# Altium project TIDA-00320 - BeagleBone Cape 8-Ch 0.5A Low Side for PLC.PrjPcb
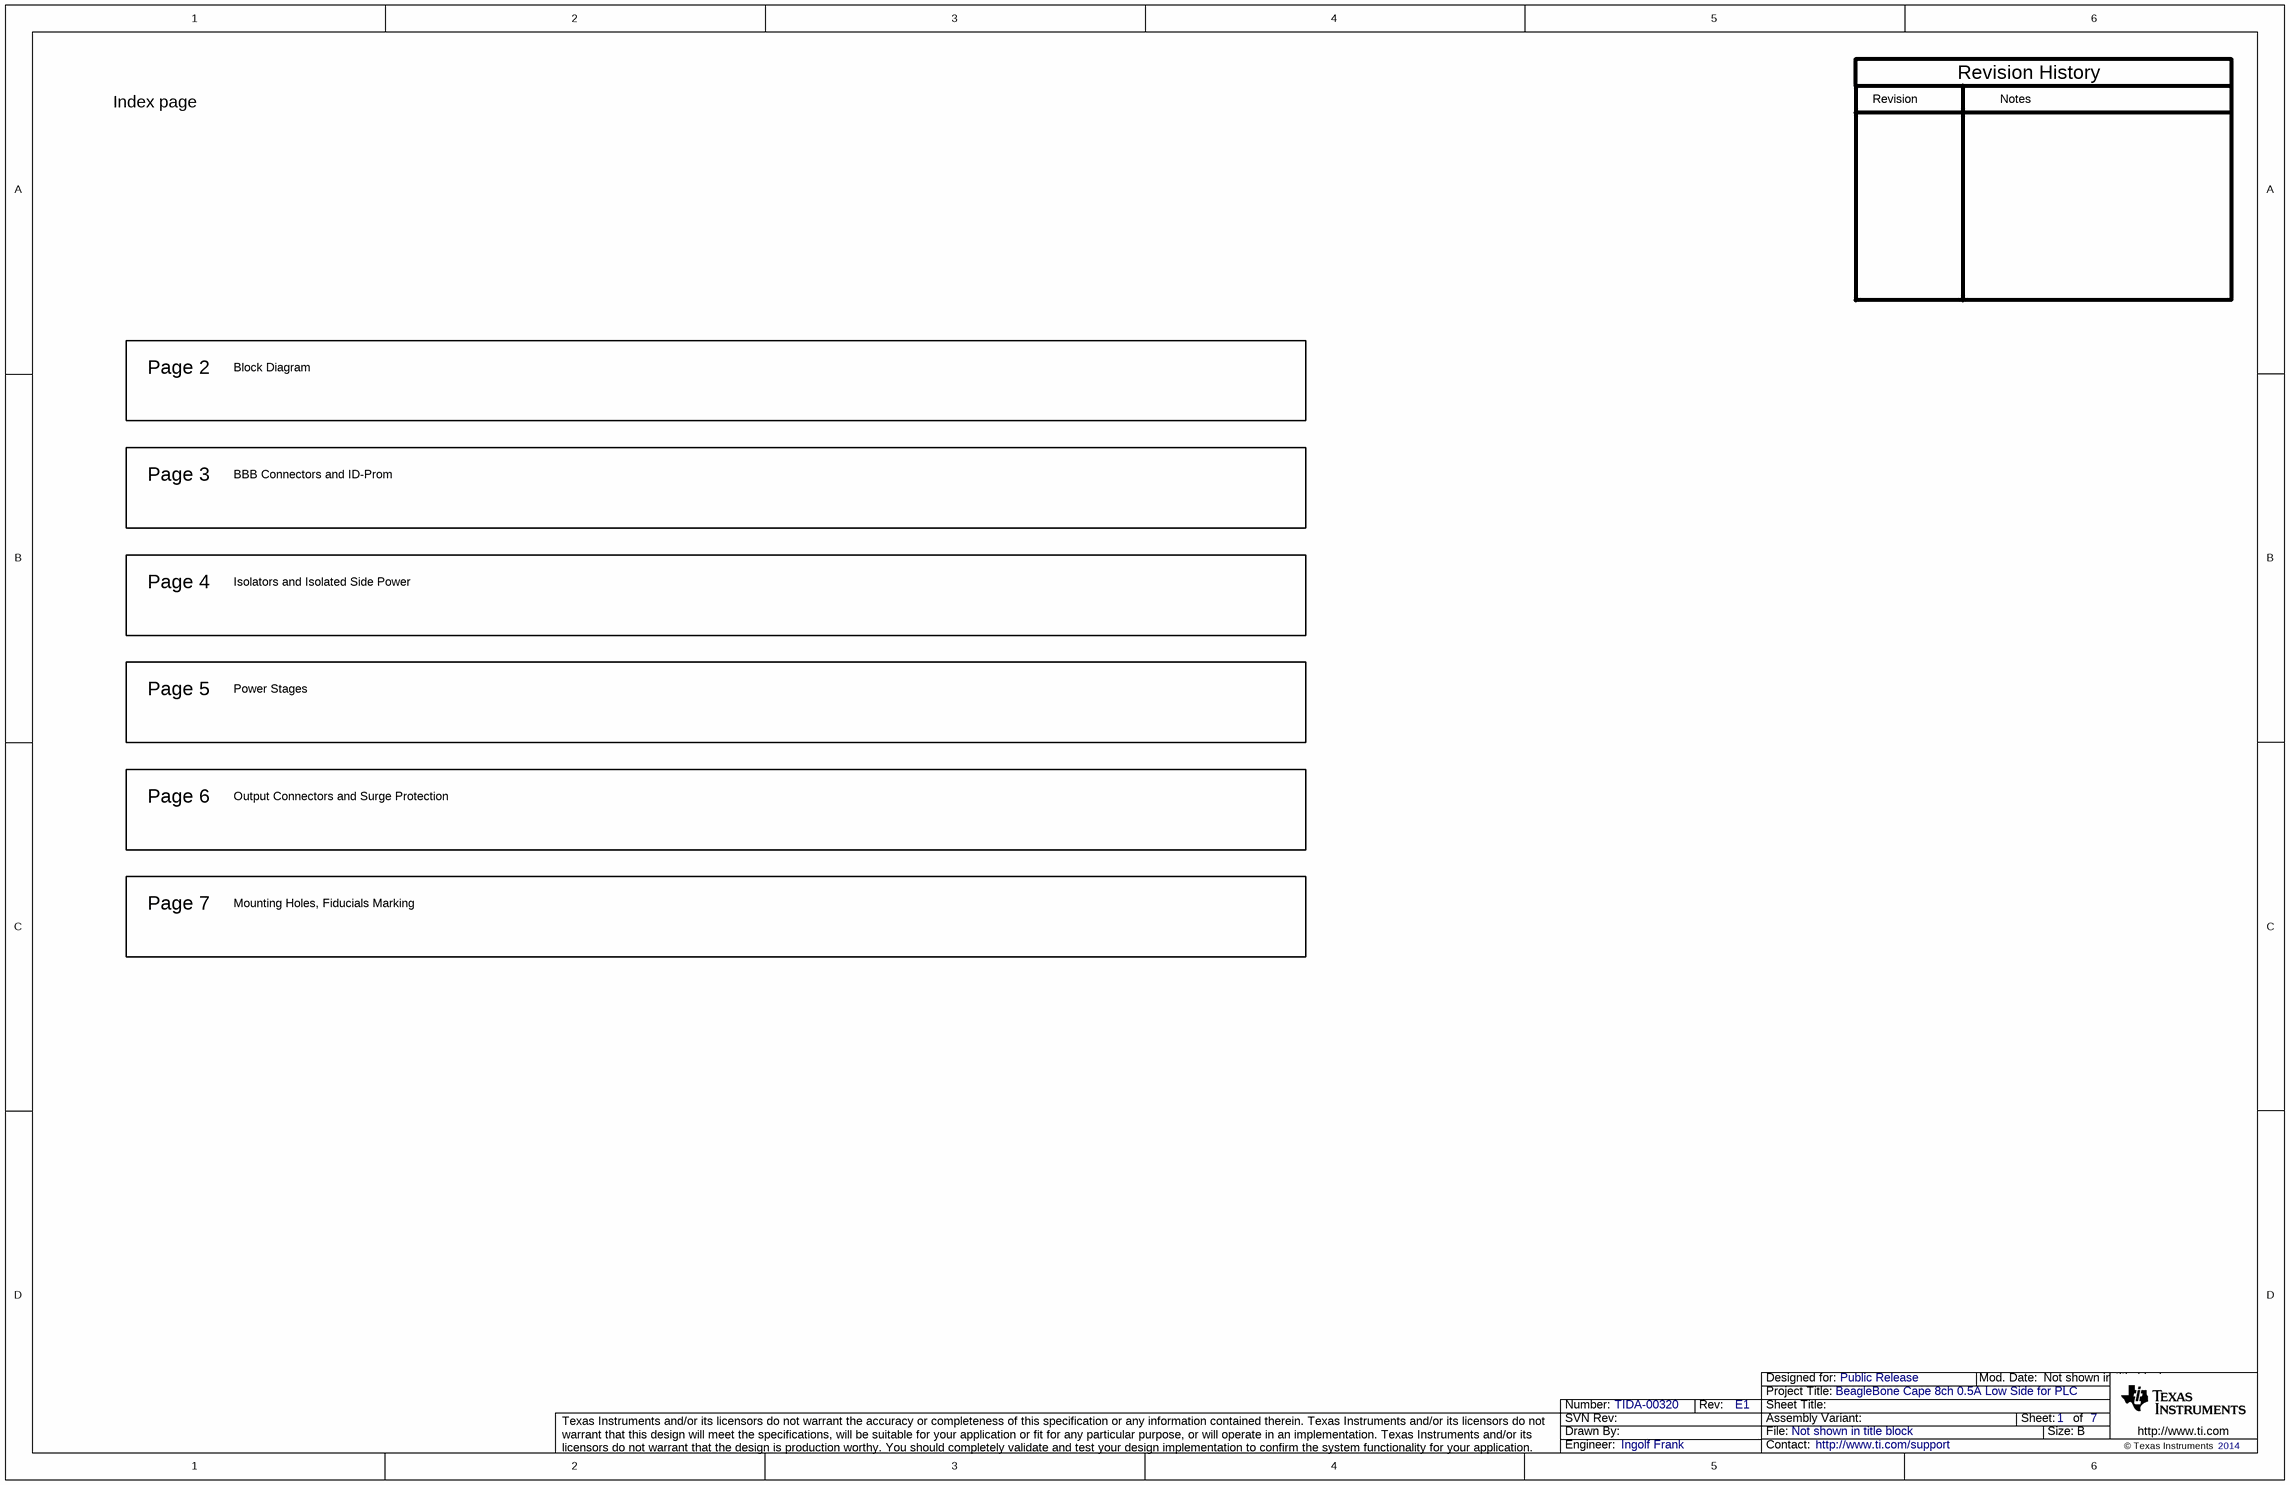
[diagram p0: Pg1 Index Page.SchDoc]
CopyrightYear: 2014; EVM_Orderable: N/A; PCB_Layout: Ingolf Frank; PCB_Rev: E1; PRJ_Customer: Public Release; PRJ_Engineer: Ingolf Frank; PRJ_Number: TIDA-00320; PRJ_Title: BeagleBone Cape 8ch 0.5A Low Side for PLC; SCH_Rev: E1; TechSupport: http://www.ti.com/support; TID: N/A
7 sheets, 117 parts. Net scope: global (net labels, ports and power ports of the same name join across sheets).
Board file: TIDA-00320_BeagleBone_Cape_8ch_LS.PcbDoc
Sheets:
  Pg1 Index Page.SchDoc
  Pg2 Block Diagram.SchDoc
  Pg3 BB Connectors.SchDoc
  Pg4 Cape Power Supply.SchDoc
  Pg5 Cape Power Stages.SchDoc
  Pg6 Cape Output.SchDoc
  Pg7 Hardware.SchDoc

## Sheet Pg1 Index Page.SchDoc
size 431 x 279 mm; Date: Not shown in title block; ApprovedBy: Not shown in title block; CheckedBy: Not shown in title block; Author: Not shown in title block; CompanyName: Not shown in title block; Engineer: Not shown in title block; Organization: Not shown in title block; Address1: Not shown in title block; Address2: Not shown in title block; Address3: Not shown in title block; Address4: Not shown in title block; DocumentNumber: 1; Revision: Use project parameter SCH_Rev; SheetNumber: 1; SheetTotal: 7; PageSetup: Record=PageOptions¦CenterHorizontal=True¦CenterVertical=True¦PrintScale=1.00¦XCorrection=1.00¦YCorrection=1.00¦PrintKind=0¦BorderSize=5000000¦LeftOffset=0¦BottomOffset=0¦Orientation=2¦PaperLength=1000¦PaperWidth=1000¦Scale=100¦PaperSource=15¦PrintQuality=600¦MediaType=1¦DitherType=10¦PaperKind=Letter¦PrintScaleMode=1

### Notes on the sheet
- Revision
- Notes
- Revision History
- Index page
- Page 2
- Block Diagram
- Page 3
- BBB Connectors and ID-Prom
- Page 4
- Isolators and Isolated Side Power
- Page 5
- Power Stages
- Page 6
- Output Connectors and Surge Protection
- Page 7
- Mounting Holes, Fiducials Marking

## Sheet Pg2 Block Diagram.SchDoc
size 431 x 279 mm; Date: Not shown in title block; ApprovedBy: Not shown in title block; CheckedBy: Not shown in title block; Author: Not shown in title block; CompanyName: Not shown in title block; Engineer: Not shown in title block; Organization: Not shown in title block; Address1: Not shown in title block; Address2: Not shown in title block; Address3: Not shown in title block; Address4: Not shown in title block; DocumentNumber: 2; Revision: Use project parameter SCH_Rev; SheetNumber: 2; SheetTotal: 7; PageSetup: Record=PageOptions¦CenterHorizontal=True¦CenterVertical=True¦PrintScale=1.00¦XCorrection=1.00¦YCorrection=1.00¦PrintKind=0¦BorderSize=5000000¦LeftOffset=0¦BottomOffset=0¦Orientation=2¦PaperLength=1000¦PaperWidth=1000¦Scale=100¦PaperSource=15¦PrintQuality=600¦MediaType=1¦DitherType=10¦PaperKind=Letter¦PrintScaleMode=1
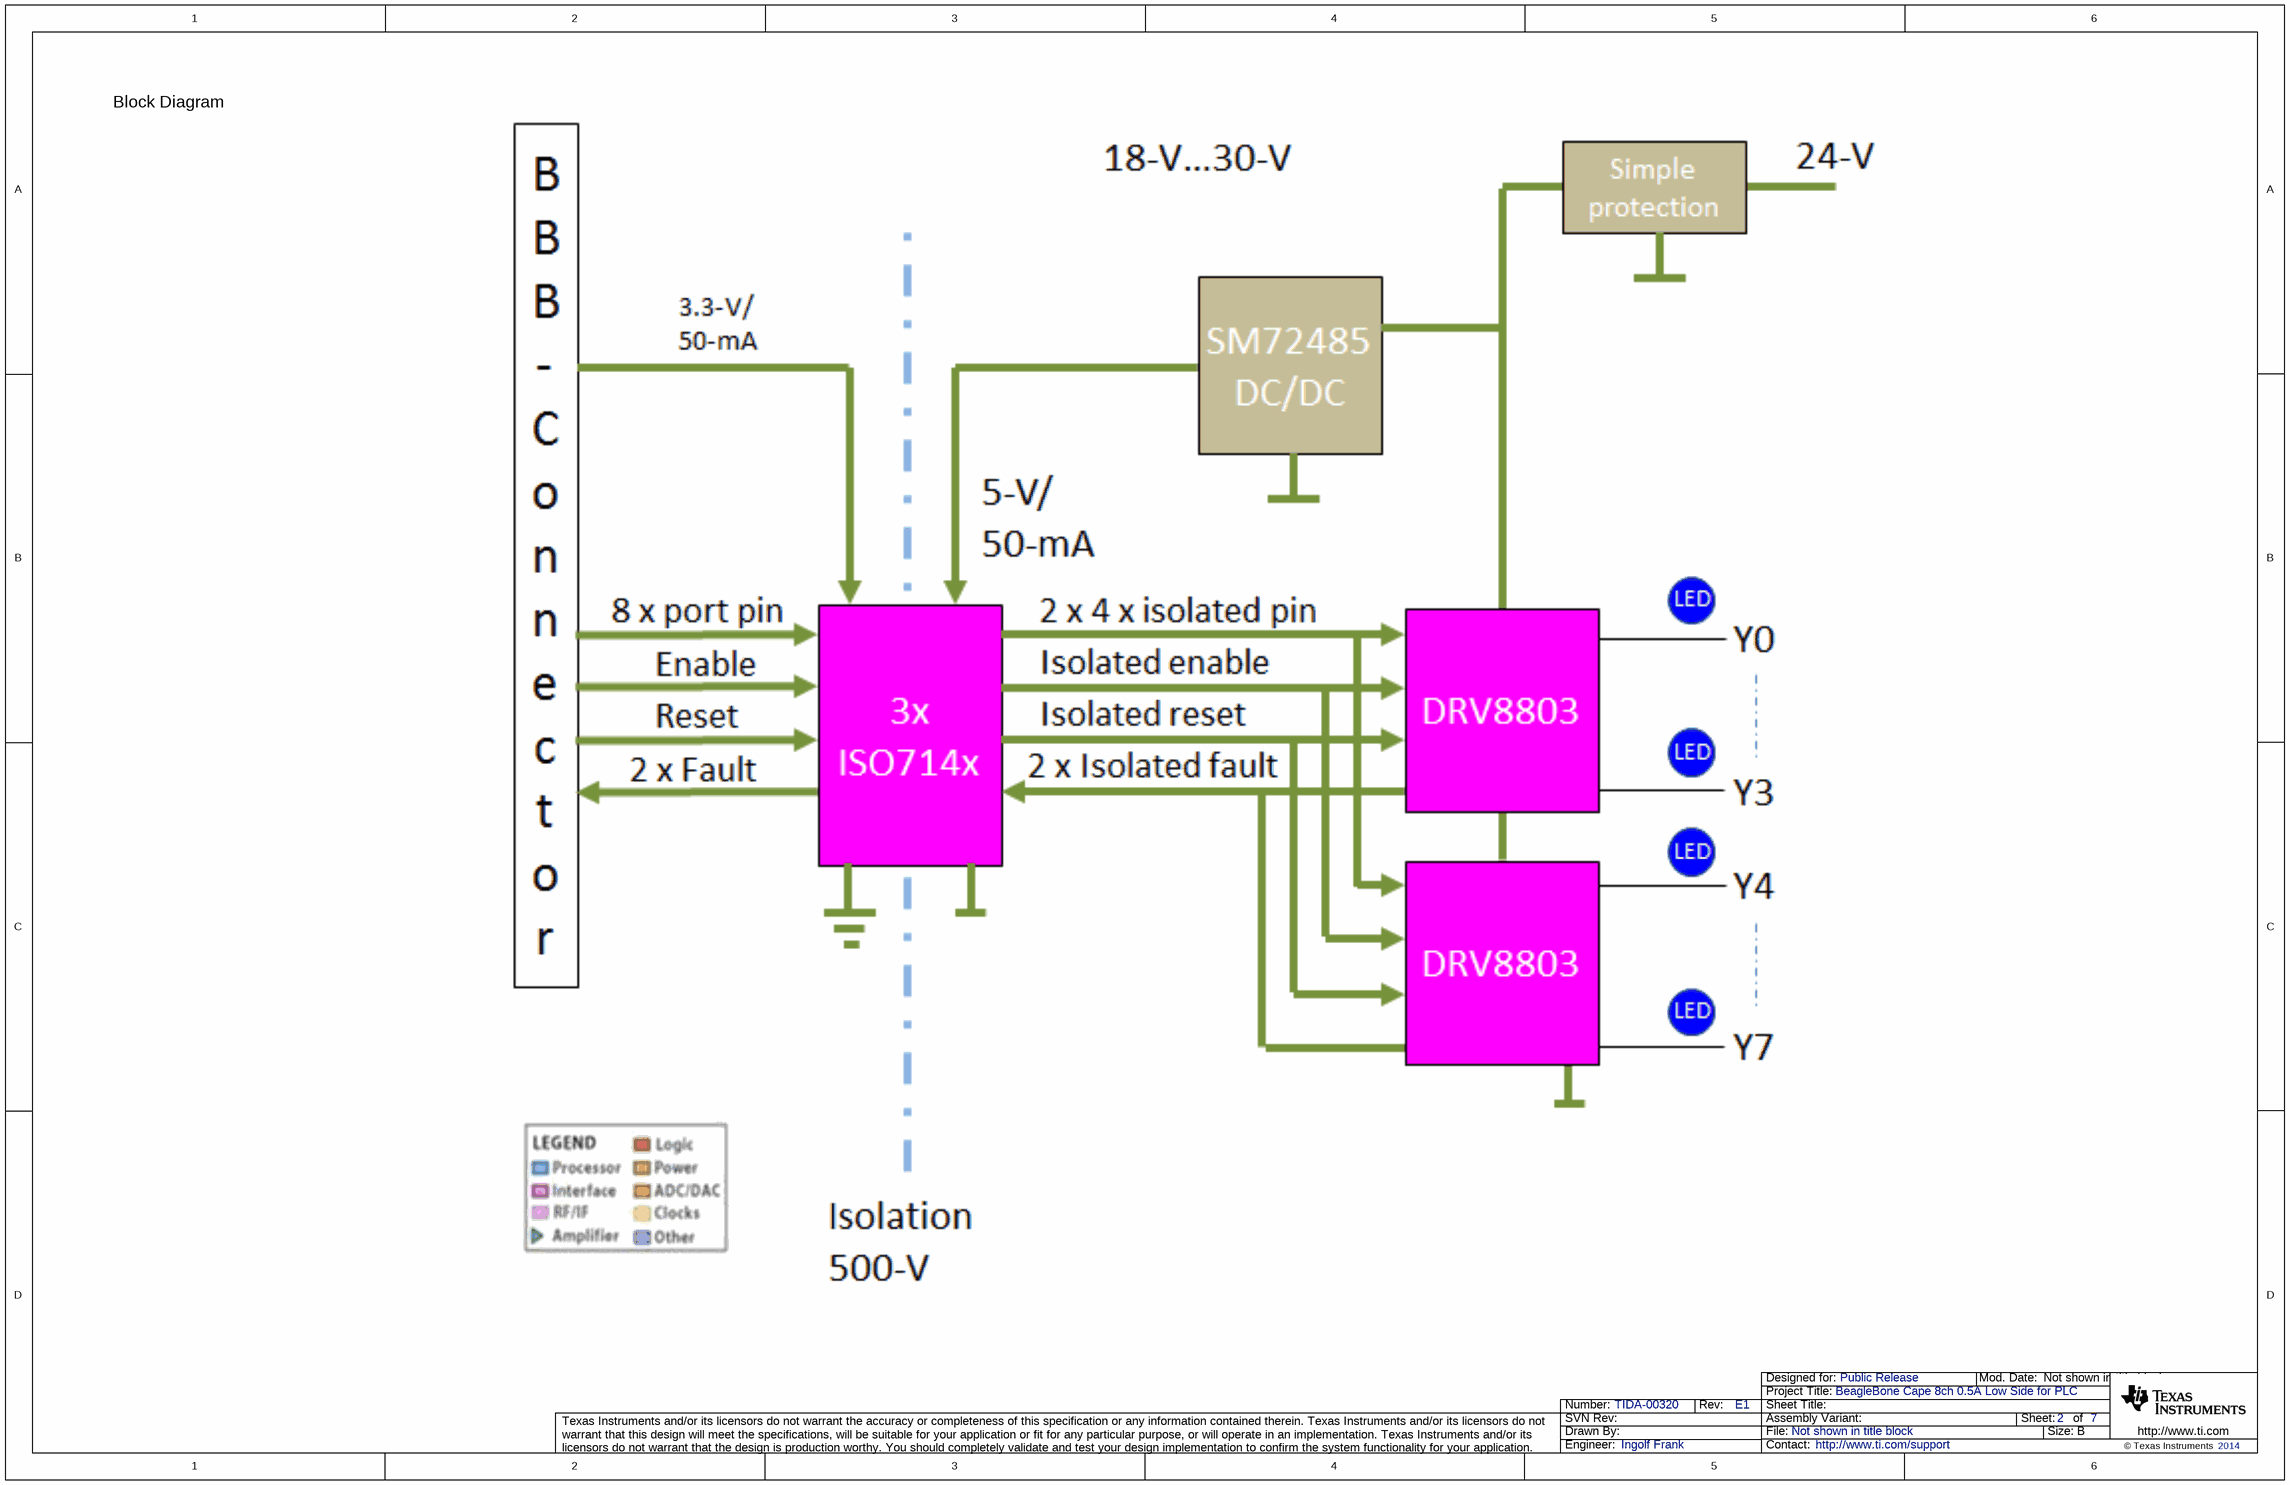
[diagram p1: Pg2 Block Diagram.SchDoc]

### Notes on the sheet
- Block Diagram

## Sheet Pg3 BB Connectors.SchDoc
size 431 x 279 mm; Date: Not shown in title block; ApprovedBy: Not shown in title block; CheckedBy: Not shown in title block; Author: Not shown in title block; CompanyName: Not shown in title block; Engineer: Not shown in title block; Organization: Not shown in title block; Address1: Not shown in title block; Address2: Not shown in title block; Address3: Not shown in title block; Address4: Not shown in title block; DocumentNumber: 3; Revision: Use project parameter SCH_Rev; SheetNumber: 3; SheetTotal: 7; PageSetup: Record=PageOptions¦CenterHorizontal=True¦CenterVertical=True¦PrintScale=1.00¦XCorrection=1.00¦YCorrection=1.00¦PrintKind=0¦BorderSize=5000000¦LeftOffset=0¦BottomOffset=0¦Orientation=2¦PaperLength=1000¦PaperWidth=1000¦Scale=100¦PaperSource=15¦PrintQuality=600¦MediaType=1¦DitherType=10¦PaperKind=Letter¦PrintScaleMode=1
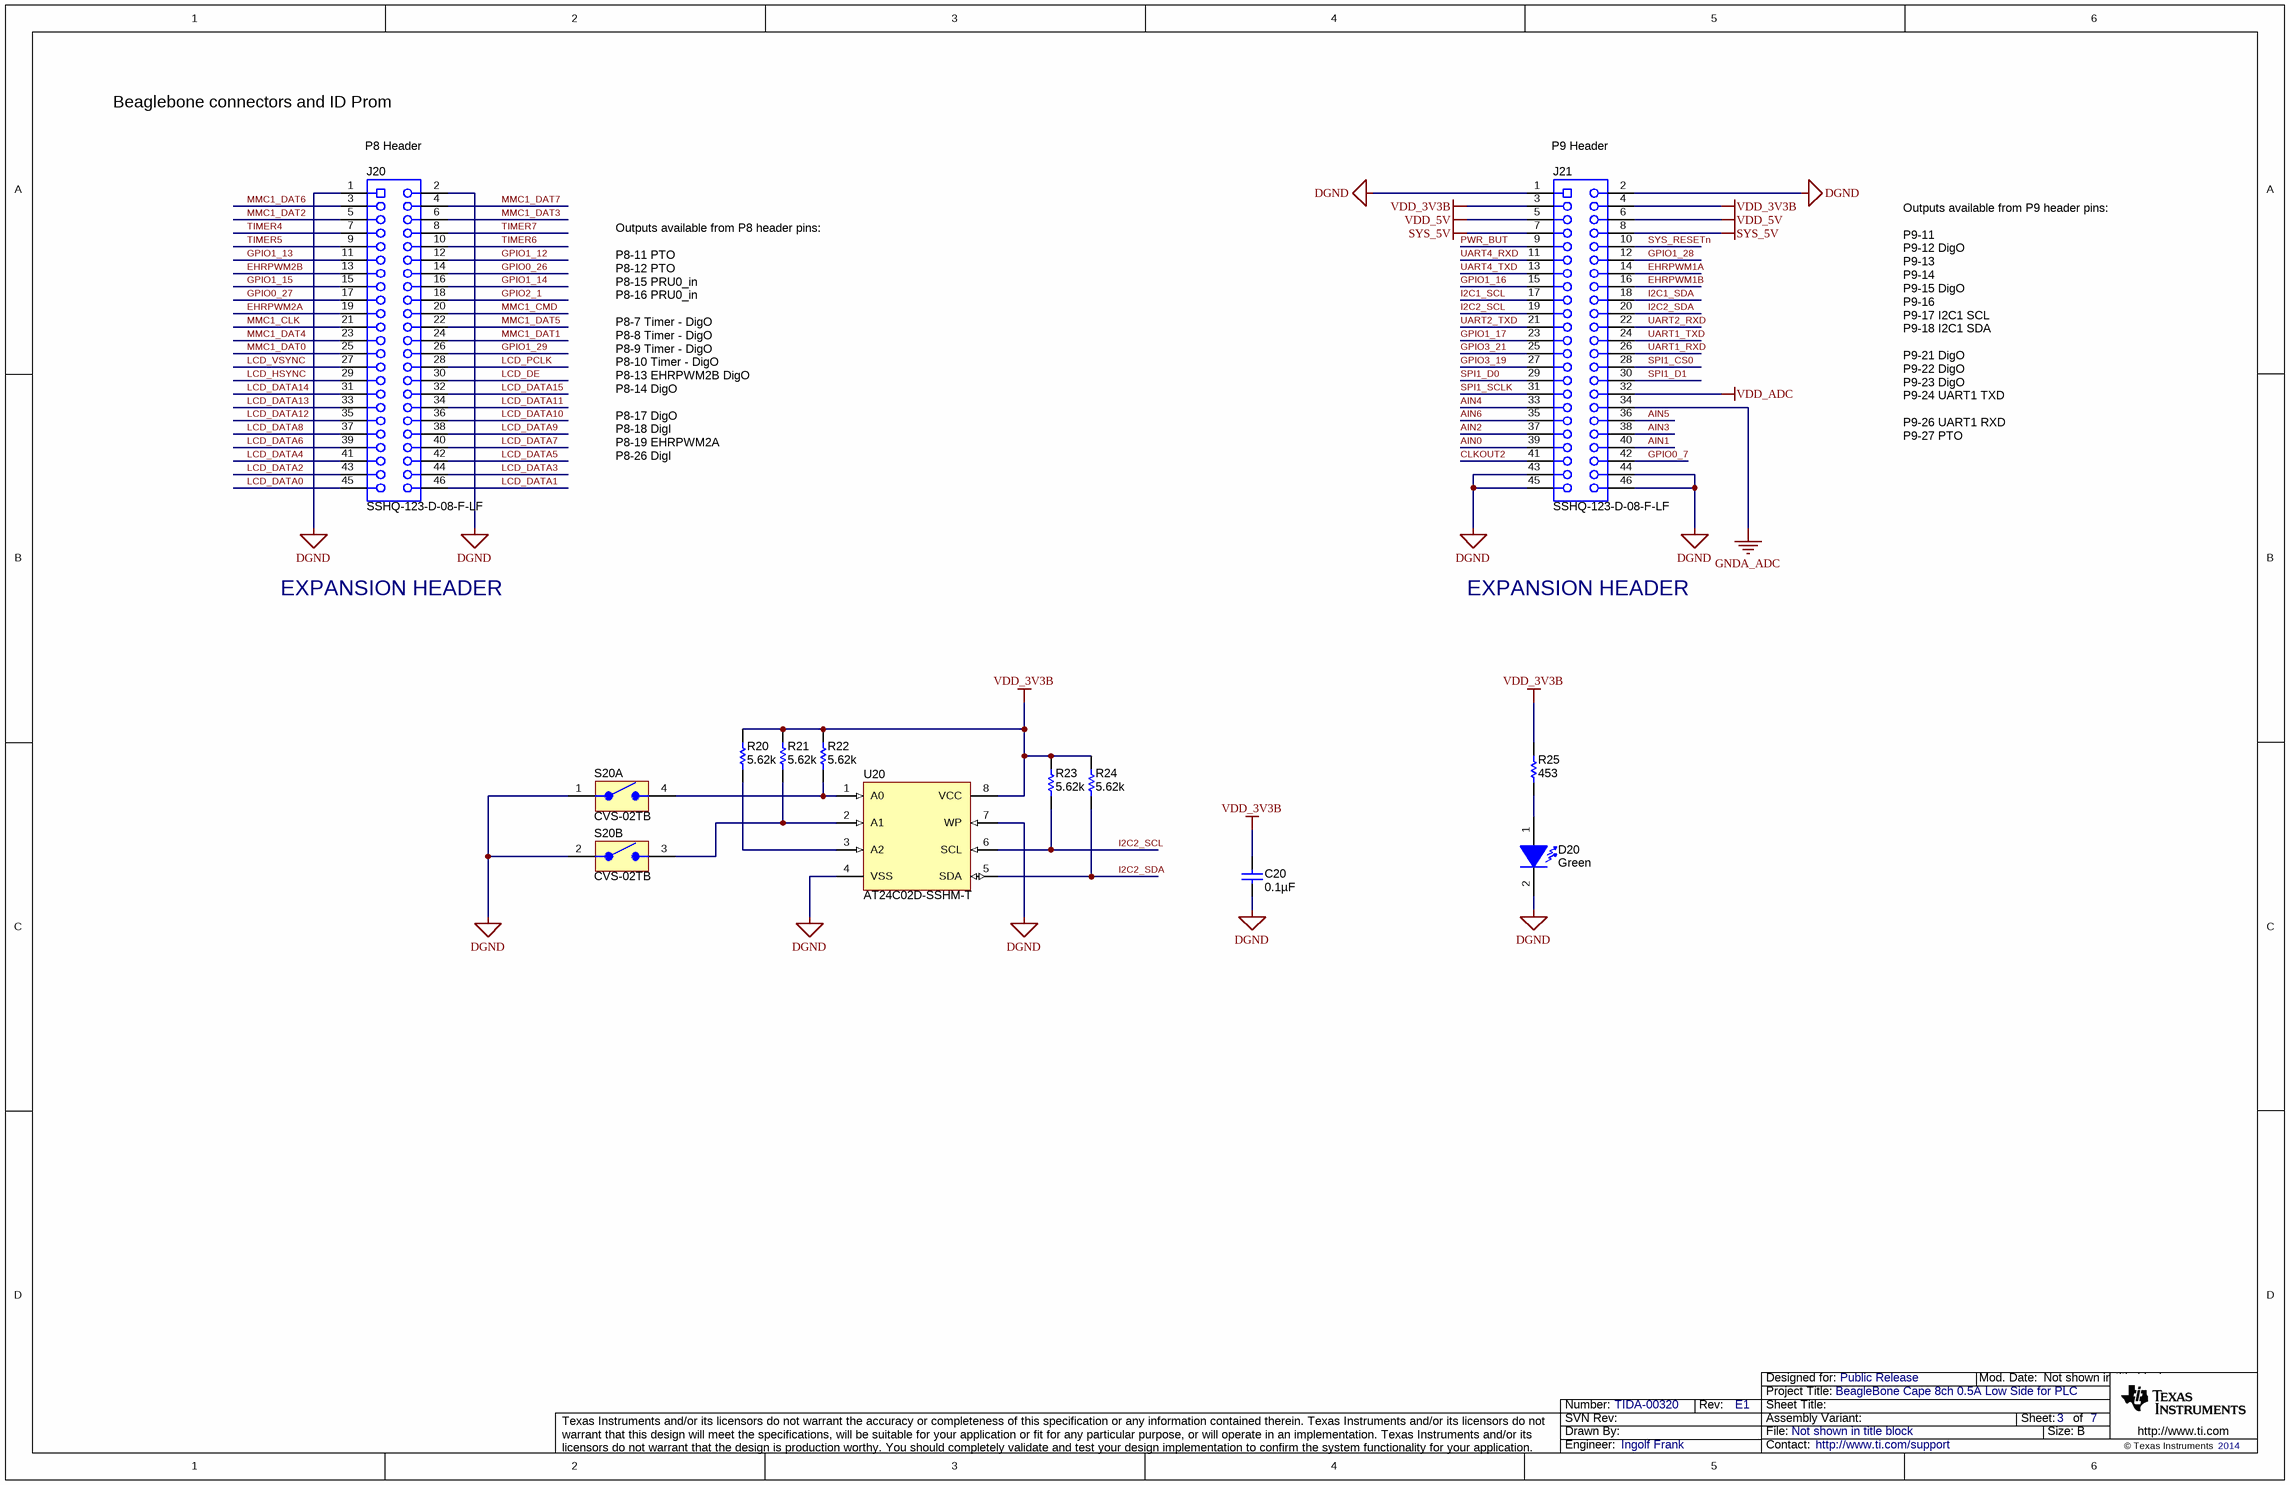
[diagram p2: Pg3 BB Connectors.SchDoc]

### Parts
C20  ValueDisplayed: 0.1µF  [0603]  (hidden comment: C0603C104K5RACTU)
D20  value Green  [LED_LTST-C190_G]  (hidden comment: LTST-C190KGKT)
J20  SSHQ-123-D-08-F-LF  [Major_SSHQ-123-D-08]
J21  SSHQ-123-D-08-F-LF  [Major_SSHQ-123-D-08]
R20  ValueDisplayed: 5.62k  [0603]  (hidden comment: CRCW06035K62FKEA)
R21  ValueDisplayed: 5.62k  [0603]  (hidden comment: CRCW06035K62FKEA)
R22  ValueDisplayed: 5.62k  [0603]  (hidden comment: CRCW06035K62FKEA)
R23  ValueDisplayed: 5.62k  [0603]  (hidden comment: CRCW06035K62FKEA)
R24  ValueDisplayed: 5.62k  [0603]  (hidden comment: CRCW06035K62FKEA)
R25  ValueDisplayed: 453  [0603]  (hidden comment: CRCW0603453RFKEA)
S20  CVS-02TB  [SW_CVS-02B]  (parts A,B of 2)
U20  AT24C02D-SSHM-T  [SOIC-8]

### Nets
DGND: C20.2 D20.2(K) J20.1 J20.2 J21.1 J21.2 J21.43 J21.44 J21.45 J21.46 S20.1 S20.2 U20.4(VSS) U20.7(WP)
GNDA_ADC: J21.34
SYS_5V: J21.7 J21.8
VDD_3V3B: C20.1 J21.3 J21.4 R20.2 R21.2 R22.2 R23.2 R24.2 R25.2 U20.8(VCC)
VDD_5V: J21.5 J21.6
VDD_ADC: J21.32
AIN0: J21.39
AIN1: J21.40
AIN2: J21.37
AIN3: J21.38
AIN4: J21.33
AIN5: J21.36
AIN6: J21.35
CLKOUT2: J21.41
EHRPWM1A: J21.14
EHRPWM1B: J21.16
EHRPWM2A: J20.19
EHRPWM2B: J20.13
GPIO0_7: J21.42
GPIO0_26: J20.14
GPIO0_27: J20.17
GPIO1_12: J20.12
GPIO1_13: J20.11
GPIO1_14: J20.16
GPIO1_15: J20.15
GPIO1_16: J21.15
GPIO1_17: J21.23
GPIO1_28: J21.12
GPIO1_29: J20.26
GPIO2_1: J20.18
GPIO3_19: J21.27
GPIO3_21: J21.25
I2C1_SCL: J21.17
I2C1_SDA: J21.18
I2C2_SCL: J21.19 R23.1 U20.6(SCL)
I2C2_SDA: J21.20 R24.1 U20.5(SDA)
LCD_DATA0: J20.45
LCD_DATA1: J20.46
LCD_DATA2: J20.43
LCD_DATA3: J20.44
LCD_DATA4: J20.41
LCD_DATA5: J20.42
LCD_DATA6: J20.39
LCD_DATA7: J20.40
LCD_DATA8: J20.37
LCD_DATA9: J20.38
LCD_DATA10: J20.36
LCD_DATA11: J20.34
LCD_DATA12: J20.35
LCD_DATA13: J20.33
LCD_DATA14: J20.31
LCD_DATA15: J20.32
LCD_DE: J20.30
LCD_HSYNC: J20.29
LCD_PCLK: J20.28
LCD_VSYNC: J20.27
MMC1_CLK: J20.21
MMC1_CMD: J20.20
MMC1_DAT0: J20.25
MMC1_DAT1: J20.24
MMC1_DAT2: J20.5
MMC1_DAT3: J20.6
MMC1_DAT4: J20.23
MMC1_DAT5: J20.22
MMC1_DAT6: J20.3
MMC1_DAT7: J20.4
PWR_BUT: J21.9
SPI1_CS0: J21.28
SPI1_D0: J21.29
SPI1_D1: J21.30
SPI1_SCLK: J21.31
SYS_RESETn: J21.10
TIMER4: J20.7
TIMER5: J20.9
TIMER6: J20.10
TIMER7: J20.8
UART1_RXD: J21.26
UART1_TXD: J21.24
UART2_RXD: J21.22
UART2_TXD: J21.21
UART4_RXD: J21.11
UART4_TXD: J21.13
NetD20_1: D20.1(A) R25.1
NetR20_1: R20.1 U20.3(A2)
NetR21_1: R21.1 S20.3 U20.2(A1)
NetR22_1: R22.1 S20.4 U20.1(A0)

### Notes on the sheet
- Beaglebone connectors and ID Prom
- (near J20) P8 Header
- (near J21) P9 Header
- Outputs available from P8 header pins:
  P8-11 PTO
  P8-12 PTO
  P8-15 PRU0_in
  P8-16 PRU0_in
  P8-7 Timer - DigO
  P8-8 Timer - DigO
  P8-9 Timer - DigO
  P8-10 Timer - DigO
  P8-13 EHRPWM2B DigO
  P8-14 DigO
  P8-17 DigO
  P8-18 DigI
  P8-19 EHRPWM2A
  P8-26 DigI
- Outputs available from P9 header pins:
  P9-11
  P9-12 DigO
  P9-13
  P9-14
  P9-15 DigO
  P9-16
  P9-17 I2C1 SCL
  P9-18 I2C1 SDA
  P9-21 DigO
  P9-22 DigO
  P9-23 DigO
  P9-24 UART1 TXD
  P9-26 UART1 RXD
  P9-27 PTO
  P9-41 PTO
- EXPANSION HEADER

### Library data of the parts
C20 = C0603C104K5RACTU: CAP, CERM, 0.1 µF, 50 V, +/- 10%, X7R, 0603; Manufacturer: Kemet; Polarized: N; CompType: Capacitor; Value: 0.1uF; U/M: EA; Cap_F: 0.0000001; Tolerance_%: 10; Value1: Unknown; VDC_V: 50; Value2: 50V; TaMin_C: -55; TaMax_C: 125
D20 = LTST-C190KGKT: LED, Green, SMD; Manufacturer: Lite-On; Type: AlInGaP; Vf_V: 2; Value2: 2V; Io_A: 0.03; Tjmax_C: 85; Value1: W; U/M: EA
J20 J21 = SSHQ-123-D-08-F-LF: Female Connector, 2.54mm, 23x2, TH; Manufacturer: Major League Electronics; SymbolCreator: Altium; CompType: Receptacle; U/M: EA
R20-R24 = CRCW06035K62FKEA: RES, 5.62 k, 1%, 0.1 W, 0603; Manufacturer: Vishay-Dale; CompType: Resistor; Value: 5.62k; Res_ohm: 5620; Value_Code: 5k62; Tolerance_%: 1; Power_W: 0.1; Value2: 0.1W; VDC_V: 75; TempCo: 100 ppm/C; EIA_Code: E96; U/M: EA
R25 = CRCW0603453RFKEA: RES, 453, 1%, 0.1 W, 0603; Manufacturer: Vishay-Dale; CompType: Resistor; Value: 453; Value_Code: 453R; Tolerance_%: 1; Power_W: 0.1; Value2: 0.1W; VDC_V: 75; TempCo: 100 ppm/C; EIA_Code: E96; U/M: EA
S20 = CVS-02TB: DIP Switch, SPST, 2Pos, Slide, SMT; Manufacturer: Copal Electronics; SymbolCreator: x0208325; VDC_V: 6; SwitchFunction: Off-On; PositionCount: 2; CurrentRating_mA: 100
U20 = AT24C02D-SSHM-T: I2C-Compatible (2-wire) Serial EEPROM 2-Kbit (256 x 8), SOIC-8; Manufacturer: Atmel; SymbolCreator: a0411947

## Sheet Pg4 Cape Power Supply.SchDoc
size 431 x 279 mm; Date: Not shown in title block; ApprovedBy: Not shown in title block; CheckedBy: Not shown in title block; Author: Not shown in title block; CompanyName: Not shown in title block; Engineer: Not shown in title block; Organization: Not shown in title block; Address1: Not shown in title block; Address2: Not shown in title block; Address3: Not shown in title block; Address4: Not shown in title block; DocumentNumber: 4; Revision: Use project parameter SCH_Rev; SheetNumber: 4; SheetTotal: 7; PageSetup: Record=PageOptions¦CenterHorizontal=True¦CenterVertical=True¦PrintScale=0.64¦XCorrection=1.00¦YCorrection=1.00¦PrintKind=0¦BorderSize=5000000¦LeftOffset=0¦BottomOffset=0¦Orientation=2¦PaperLength=1000¦PaperWidth=1000¦Scale=100¦PaperSource=15¦PrintQuality=600¦MediaType=1¦DitherType=10¦PrintScaleMode=1¦PaperKind=Letter
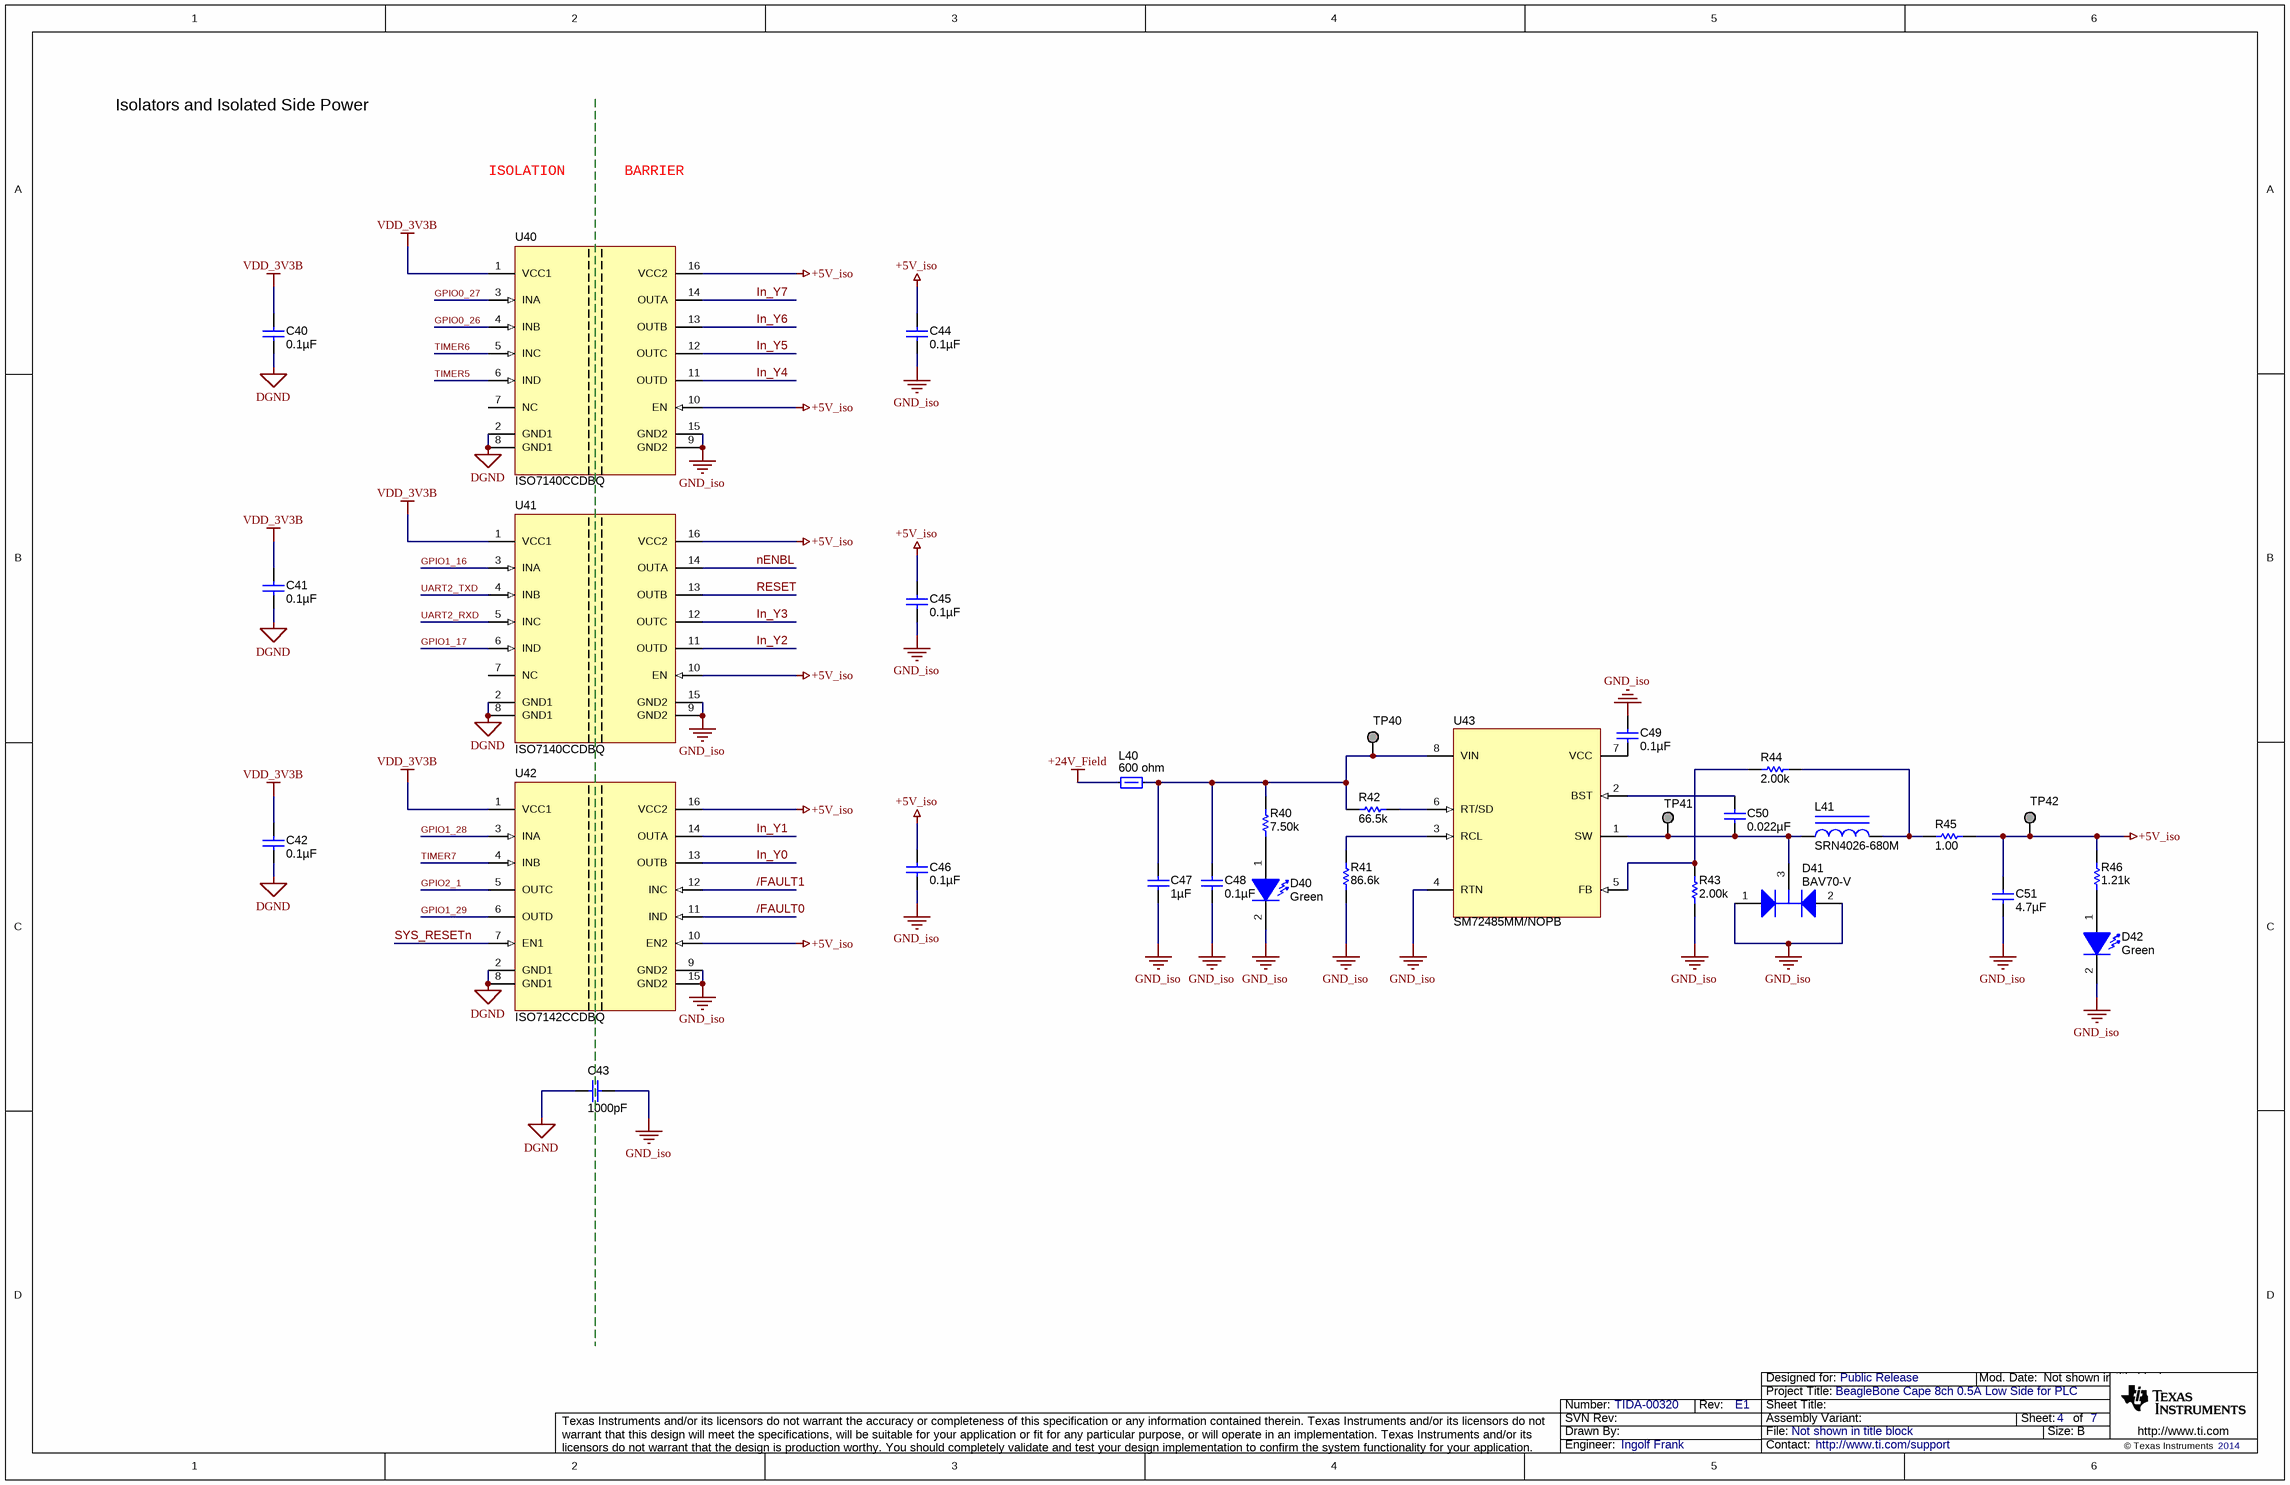
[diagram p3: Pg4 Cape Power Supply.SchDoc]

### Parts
C40  ValueDisplayed: 0.1µF  [0603]  (hidden comment: C0603C104K5RACTU)
C41  ValueDisplayed: 0.1µF  [0603]  (hidden comment: C0603C104K5RACTU)
C42  ValueDisplayed: 0.1µF  [0603]  (hidden comment: C0603C104K5RACTU)
C43  value 1000pF  [1206]  (hidden comment: 202R18W102KV4E)
C44  ValueDisplayed: 0.1µF  [0603]  (hidden comment: C0603C104K5RACTU)
C45  ValueDisplayed: 0.1µF  [0603]  (hidden comment: C0603C104K5RACTU)
C46  ValueDisplayed: 0.1µF  [0603]  (hidden comment: C0603C104K5RACTU)
C47  ValueDisplayed: 1µF  [1206]  (hidden comment: C3216X7R1H105K)
C48  ValueDisplayed: 0.1µF  [0603]  (hidden comment: C0603C104K5RACTU)
C49  ValueDisplayed: 0.1µF  [0603]  (hidden comment: C0603C104K5RACTU)
C50  ValueDisplayed: 0.022µF  [0603]  (hidden comment: C0603C223K5RACTU)
C51  ValueDisplayed: 4.7µF  [0603]  (hidden comment: C0603C475K8PACTU)
D40  value Green  [LED_LTST-C190_G]  (hidden comment: LTST-C190KGKT)
D41  BAV70-V  [SOT-23]
D42  value Green  [LED_LTST-C190_G]  (hidden comment: LTST-C190KGKT)
L40  value 600 ohm  [0603]  (hidden comment: BLM18KG601SN1D)
L41  SRN4026-680M  [SRN4026]
R40  ValueDisplayed: 7.50k  [0603]  (hidden comment: CRCW06037K50FKEA)
R41  value 86.6k  [0603]  (hidden comment: CRCW060386K6FKEA)
R42  value 66.5k  [0603]  (hidden comment: CRCW060366K5FKEA)
R43  ValueDisplayed: 2.00k  [0603]  (hidden comment: CRCW06032K00FKEA)
R44  ValueDisplayed: 2.00k  [0603]  (hidden comment: CRCW06032K00FKEA)
R45  ValueDisplayed: 1.00  [0603]  (hidden comment: CRCW06031R00FKEA)
R46  ValueDisplayed: 1.21k  [0603]  (hidden comment: CRCW06031K21FKEA)
TP40  Pogo Pad  [PogoPad]  (value not drawn)  (no BOM)
TP41  Pogo Pad  [PogoPad]  (value not drawn)  (no BOM)
TP42  Pogo Pad  [PogoPad]  (value not drawn)  (no BOM)
U40  ISO7140CCDBQ  [DBQ0016A_N]
U41  ISO7140CCDBQ  [DBQ0016A_N]
U42  ISO7142CCDBQ  [DBQ0016A_N]
U43  SM72485MM/NOPB  [DGK0008A_N]

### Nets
+5V_iso: C44.1 C45.1 C46.1 C51.1 R45.2 R46.1 TP42.1 U40.10(EN) U40.16(VCC2) U41.10(EN) U41.16(VCC2) U42.10(EN2) U42.16(VCC2)
+24V_Field: L40.1
DGND: C40.2 C41.2 C42.2 C43.2 U40.2(GND1) U40.8(GND1) U41.2(GND1) U41.8(GND1) U42.2(GND1) U42.8(GND1)
GND_iso: C43.1 C44.2 C45.2 C46.2 C47.2 C48.2 C49.1 C51.2 D40.2(K) D41.1(A) D41.2(K) D42.2(K) R41.1 R43.1 U40.9(GND2) U40.15(GND2) U41.9(GND2) U41.15(GND2) U42.9(GND2) U42.15(GND2) U43.4(RTN)
VDD_3V3B: C40.1 C41.1 C42.1 U40.1(VCC1) U41.1(VCC1) U42.1(VCC1)
/FAULT0: U42.11(IND)
/FAULT1: U42.12(INC)
GPIO0_26: U40.4(INB)
GPIO0_27: U40.3(INA)
GPIO1_16: U41.3(INA)
GPIO1_17: U41.6(IND)
GPIO1_28: U42.3(INA)
GPIO1_29: U42.6(OUTD)
GPIO2_1: U42.5(OUTC)
In_Y0: U42.13(OUTB)
In_Y1: U42.14(OUTA)
In_Y2: U41.11(OUTD)
In_Y3: U41.12(OUTC)
In_Y4: U40.11(OUTD)
In_Y5: U40.12(OUTC)
In_Y6: U40.13(OUTB)
In_Y7: U40.14(OUTA)
nENBL: U41.14(OUTA)
RESET: U41.13(OUTB)
SYS_RESETn: U42.7(EN1)
TIMER5: U40.6(IND)
TIMER6: U40.5(INC)
TIMER7: U42.4(INB)
UART2_RXD: U41.5(INC)
UART2_TXD: U41.4(INB)
NetC47_1: C47.1 C48.1 L40.2 R40.2 R42.2 TP40.1 U43.8(VIN)
NetC49_2: C49.2 U43.7(VCC)
NetC50_1: C50.1 U43.2(BST)
NetC50_2: C50.2 D41.3(C) L41.1 TP41.1 U43.1(SW)
NetD40_1: D40.1(A) R40.1
NetD42_1: D42.1(A) R46.2
NetL41_2: L41.2 R44.1 R45.1
NetR41_2: R41.2 U43.3(RCL)
NetR42_1: R42.1 U43.6(RT/SD)
NetR43_2: R43.2 R44.2 U43.5(FB)

Not connected (* = marked no-connect by the designer): U40 7(NC); U41 7(NC)

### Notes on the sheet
- Isolators and Isolated Side Power
- ISOLATION       BARRIER

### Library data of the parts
C40-C42 C44-C46 C49 = C0603C104K5RACTU: as C20 on sheet Pg3 BB Connectors
C43 = 202R18W102KV4E: CAP, CERM, 1000pF, 2KV 10% X7R 1206; Manufacturer: Johanson Dielectrics Inc; Polarized: N; CompType: Capacitor; Cap_F: 0.000000001; Tolerance_%: 0
C47 = C3216X7R1H105K: CAP, CERM, 1uF, 50V, +/-10%, X7R, 1206; Manufacturer: TDK; Polarized: N; CompType: Capacitor; U/M: EA; Cap_F: 0.000001; Tolerance_%: 10; ESR_Ohm: 0.01; Value1: 0.01 ohm; VDC_V: 50; IRMS_A: 3.2; TaMin_C: -55; TaMax_C: 125
C48 = C0603C104K5RACTU: CAP, CERM, 0.1uF, 50V, +/-10%, X7R, 0603; Manufacturer: Kemet; Polarized: N; CompType: Capacitor; U/M: EA; Cap_F: 0.0000001; Tolerance_%: 10; Value1: Unknown; VDC_V: 50; TaMin_C: -55; TaMax_C: 125
C50 = C0603C223K5RACTU: CAP, CERM, 0.022 µF, 50 V, +/- 10%, X7R, 0603; Manufacturer: Kemet; Polarized: N; CompType: Capacitor; Value: 0.022uF; U/M: EA; Cap_F: 0.000000022; Tolerance_%: 10; Value1: Unknown; VDC_V: 50; Value2: 50V; TaMin_C: -55; TaMax_C: 125
C51 = C0603C475K8PACTU: CAP, CERM, 4.7 µF, 10 V, +/- 10%, X5R, 0603; Manufacturer: Kemet; Polarized: N; CompType: Capacitor; Value: 4.7uF; U/M: EA; Cap_F: 0.0000047; Tolerance_%: 10; ESR_ohm: 0.006; Value1: 0.006 ohm; Value2: 10V; IRMS_A: 7.24; TaMin_C: -55; TaMax_C: 85
D40 D42 = LTST-C190KGKT: as D20 on sheet Pg3 BB Connectors
D41 = BAV70-V: Diode, Switching, 70 V, 0.25 A, SOT-23; Manufacturer: Vishay-Semiconductor; Value: 70V; SymbolCreator: a0412235; U/M: EA; Vf_V: 1.25; Value1: 0.25A; Value2: 1.25V; Io_A: 0.25; Vr_V: 70; TJmax_C: 150; RJC_CperW: 430
L40 = BLM18KG601SN1D: Ferrite Bead, 600 ohm @ 100 MHz, 1.3 A, 0603; Manufacturer: MuRata; Imax_A: 1.3; DCR_ohm: 0.15; Value1: 0.15 ohm; Value2: 1.3A; ZTyp@100MHz_Ohm: 600
L41 = SRN4026-680M: Inductor, Wirewound, Ferrite, 68uH, 0.35A, 0.852 ohm, SMD; Manufacturer: Bourns; Ind_H: 68.0E-6; ValueDisplayed: 68µH; Imax_A: 0.35; Irms: 0.35A @ 40C rise; Isat: 0.35A @ 30% inductance drop; DCR_ohm: 0.852
R40 = CRCW06037K50FKEA: RES, 7.50 k, 1%, 0.1 W, 0603; Manufacturer: Vishay-Dale; CompType: Resistor; Value: 7.50k; Res_ohm: 7500; Value_Code: 7k50; Tolerance_%: 1; Power_W: 0.1; Value2: 0.1W; VDC_V: 75; TempCo: 100 ppm/C; EIA_Code: E96; U/M: EA
R41 = CRCW060386K6FKEA: RES, 86.6k ohm, 1%, 0.1W, 0603; Manufacturer: Vishay-Dale; CompType: Resistor; Res_ohm: 86600; Value_Code: 86k6; Tolerance_%: 1; Power_W: 0.1; VDC_V: 75; TempCo: 100 ppm/C; EIA_Code: E96; U/M: EA
R42 = CRCW060366K5FKEA: RES, 66.5k ohm, 1%, 0.1W, 0603; Manufacturer: Vishay-Dale; CompType: Resistor; Res_ohm: 66500; Value_Code: 66k5; Tolerance_%: 1; Power_W: 0.1; VDC_V: 75; TempCo: 100 ppm/C; EIA_Code: E96; U/M: EA
R43 R44 = CRCW06032K00FKEA: RES, 2.00 k, 1%, 0.1 W, 0603; Manufacturer: Vishay-Dale; CompType: Resistor; Value: 2.00k; Res_ohm: 2000; Value_Code: 2k00; Tolerance_%: 1; Power_W: 0.1; Value2: 0.1W; VDC_V: 75; TempCo: 100 ppm/C; EIA_Code: E96; U/M: EA
R45 = CRCW06031R00FKEA: RES, 1.00, 1%, 0.1 W, 0603; Manufacturer: Vishay-Dale; CompType: Resistor; Value: 1.00; Res_ohm: 1; Value_Code: 1R00; Power_W: 0.1; Value2: 0.1W; VDC_V: 75; TempCo: 100 ppm/C; EIA_Code: E96; U/M: EA
R46 = CRCW06031K21FKEA: RES, 1.21 k, 1%, 0.1 W, 0603; Manufacturer: Vishay-Dale; CompType: Resistor; Value: 1.21k; Res_ohm: 1210; Value_Code: 1k21; Tolerance_%: 1; Power_W: 0.1; Value2: 0.1W; VDC_V: 75; TempCo: 100 ppm/C; EIA_Code: E96; U/M: EA
TP40-TP42 = PogoPad: Pad for Pogo Pin Connector; SymbolCreator: codlsc
U40 U41 = ISO7140CCDBQ: 4242-VPK Small-Footprint and Low-Power Quad Channels Digital Isolators, DBQ0016A; Alternate Manufacturer: None; Manufacturer: Texas Instruments; SymbolCreator: a0799628; CompType: IC; U/M: EA
U42 = ISO7142CCDBQ: 4242-V PK Small-Footprint and Low-Power Quad Channel Digital Isolator, DBQ0016A; Alternate Manufacturer: None; Manufacturer: Texas Instruments; SymbolCreator: Altium; CompType: IC; U/M: EA
U43 = SM72485MM/NOPB: SolarMagic 100V, 150 mA Constant On-Time Buck Switching Regulator, DGK0008A; Manufacturer: Texas Instruments; CompType: IC; SymbolCreator: Altium; U/M: EA

## Sheet Pg5 Cape Power Stages.SchDoc: LED drivers and power stages
size 431 x 279 mm; Date: Not shown in title block; ApprovedBy: Not shown in title block; CheckedBy: Not shown in title block; Author: Not shown in title block; CompanyName: Not shown in title block; DrawnBy: Ingolf Frank; Engineer: Not shown in title block; Organization: Not shown in title block; Address1: Not shown in title block; Address2: Not shown in title block; Address3: Not shown in title block; Address4: Not shown in title block; DocumentNumber: 5; Revision: Use project parameter SCH_Rev; SheetNumber: 5; SheetTotal: 7; PageSetup: Record=PageOptions¦CenterHorizontal=True¦CenterVertical=True¦PrintScale=0.64¦XCorrection=1.00¦YCorrection=1.00¦PrintKind=0¦BorderSize=5000000¦LeftOffset=0¦BottomOffset=0¦Orientation=2¦PaperLength=1000¦PaperWidth=1000¦Scale=100¦PaperSource=15¦PrintQuality=600¦MediaType=1¦DitherType=10¦PaperKind=Letter¦PrintScaleMode=1
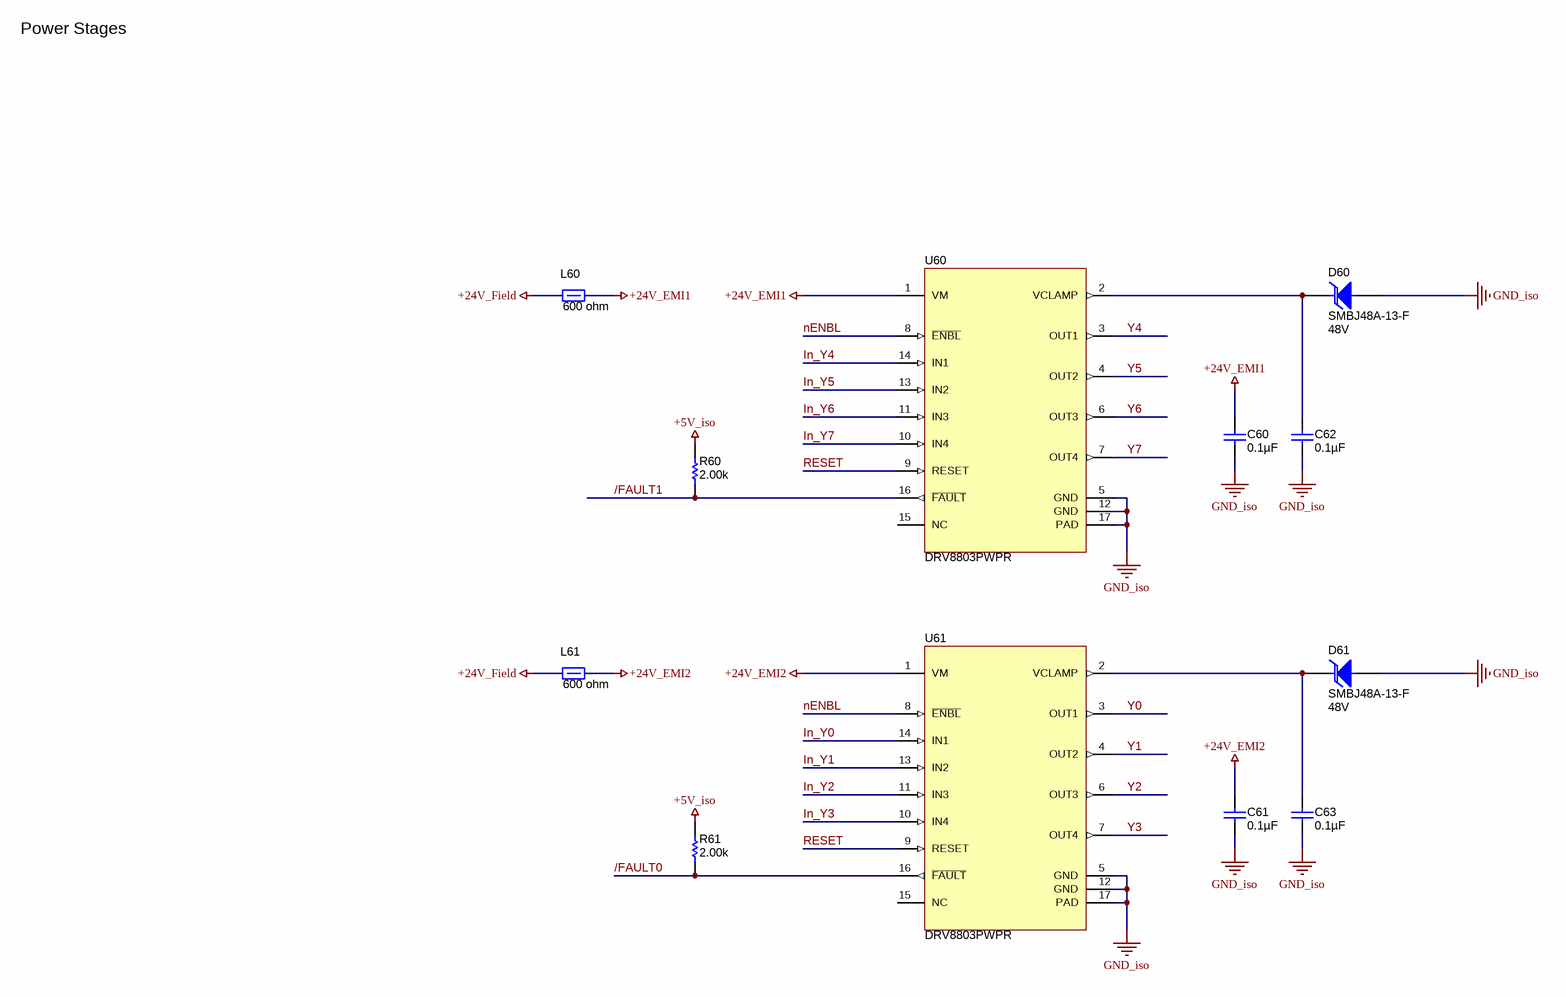
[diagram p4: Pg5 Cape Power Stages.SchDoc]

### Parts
C60  ValueDisplayed: 0.1µF  [0603]  (hidden comment: C0603C104K5RACTU)
C61  ValueDisplayed: 0.1µF  [0603]  (hidden comment: C0603C104K5RACTU)
C62  ValueDisplayed: 0.1µF  [0805_HV]  (hidden comment: CL21B104KCFSFNE)
C63  ValueDisplayed: 0.1µF  [0805_HV]  (hidden comment: CL21B104KCFSFNE)
D60  SMBJ48A-13-F  value 48V  [SMB]
D61  SMBJ48A-13-F  value 48V  [SMB]
L60  value 600 ohm  [0603]  (hidden comment: BLM18KG601SN1D)
L61  value 600 ohm  [0603]  (hidden comment: BLM18KG601SN1D)
R60  ValueDisplayed: 2.00k  [0603]  (hidden comment: CRCW06032K00FKEA)
R61  ValueDisplayed: 2.00k  [0603]  (hidden comment: CRCW06032K00FKEA)
U60  DRV8803PWPR  [PWP0016D_N]
U61  DRV8803PWPR  [PWP0016D_N]

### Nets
+5V_iso: R60.1 R61.1
+24V_EMI1: C60.1 L60.2 U60.1(VM)
+24V_EMI2: C61.1 L61.2 U61.1(VM)
+24V_Field: L60.1 L61.1
GND_iso: C60.2 C61.2 C62.2 C63.2 D60.2(A) D61.2(A) U60.5(GND) U60.12(GND) U60.17(PAD) U61.5(GND) U61.12(GND) U61.17(PAD)
/FAULT0: R61.2 U61.16(~{FAULT})
/FAULT1: R60.2 U60.16(~{FAULT})
In_Y0: U61.14(IN1)
In_Y1: U61.13(IN2)
In_Y2: U61.11(IN3)
In_Y3: U61.10(IN4)
In_Y4: U60.14(IN1)
In_Y5: U60.13(IN2)
In_Y6: U60.11(IN3)
In_Y7: U60.10(IN4)
nENBL: U60.8(~{ENBL}) U61.8(~{ENBL})
RESET: U60.9(RESET) U61.9(RESET)
Y0: U61.3(OUT1)
Y1: U61.4(OUT2)
Y2: U61.6(OUT3)
Y3: U61.7(OUT4)
Y4: U60.3(OUT1)
Y5: U60.4(OUT2)
Y6: U60.6(OUT3)
Y7: U60.7(OUT4)
NetC62_1: C62.1 D60.1(K) U60.2(VCLAMP)
NetC63_1: C63.1 D61.1(K) U61.2(VCLAMP)

Not connected (* = marked no-connect by the designer): U60 15(NC); U61 15(NC)

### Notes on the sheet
- Power Stages

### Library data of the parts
C60 C61 = C0603C104K5RACTU: as C20 on sheet Pg3 BB Connectors
C62 C63 = CL21B104KCFSFNE: CAP, CERM, 0.1 µF, 100 V, +/- 10%, X7R, 0805; Manufacturer: Samsung; Polarized: N; CompType: Capacitor; Value: 0.1uF; U/M: EA; Cap_F: 0.0000001; Tolerance_%: 10; Value1: Unknown; VDC_V: 100; Value2: 100V; TaMin_C: -55; TaMax_C: 125; Cap_Case: 0805
D60 D61 = SMBJ48A-13-F: Diode, TVS, Uni, 48V, 600W, SMB; Manufacturer: Diodes Inc.; U/M: EA; Power_W: 5; Vr_V: 48; Value1: 5W
L60 L61 = BLM18KG601SN1D: as L40 on sheet Pg4 Cape Power Supply
R60 R61 = CRCW06032K00FKEA: as R43 on sheet Pg4 Cape Power Supply
U60 U61 = DRV8803PWPR: Quad Low-Side Driver IC, PWP0016D; Manufacturer: Texas Instruments; SymbolCreator: Altium; CompType: d; U/M: EA

## Sheet Pg6 Cape Output.SchDoc
size 431 x 279 mm; Date: Not shown in title block; ApprovedBy: Not shown in title block; CheckedBy: Not shown in title block; Author: Not shown in title block; CompanyName: Not shown in title block; Engineer: Not shown in title block; Organization: Not shown in title block; Address1: Not shown in title block; Address2: Not shown in title block; Address3: Not shown in title block; Address4: Not shown in title block; DocumentNumber: 6; Revision: Use project parameter SCH_Rev; SheetNumber: 6; SheetTotal: 7; PageSetup: Record=PageOptions¦CenterHorizontal=True¦CenterVertical=True¦PrintScale=1.00¦XCorrection=1.00¦YCorrection=1.00¦PrintKind=0¦BorderSize=5000000¦LeftOffset=0¦BottomOffset=0¦Orientation=2¦PaperLength=1000¦PaperWidth=1000¦Scale=100¦PaperSource=15¦PrintQuality=600¦MediaType=1¦DitherType=10¦PaperKind=Letter¦PrintScaleMode=1
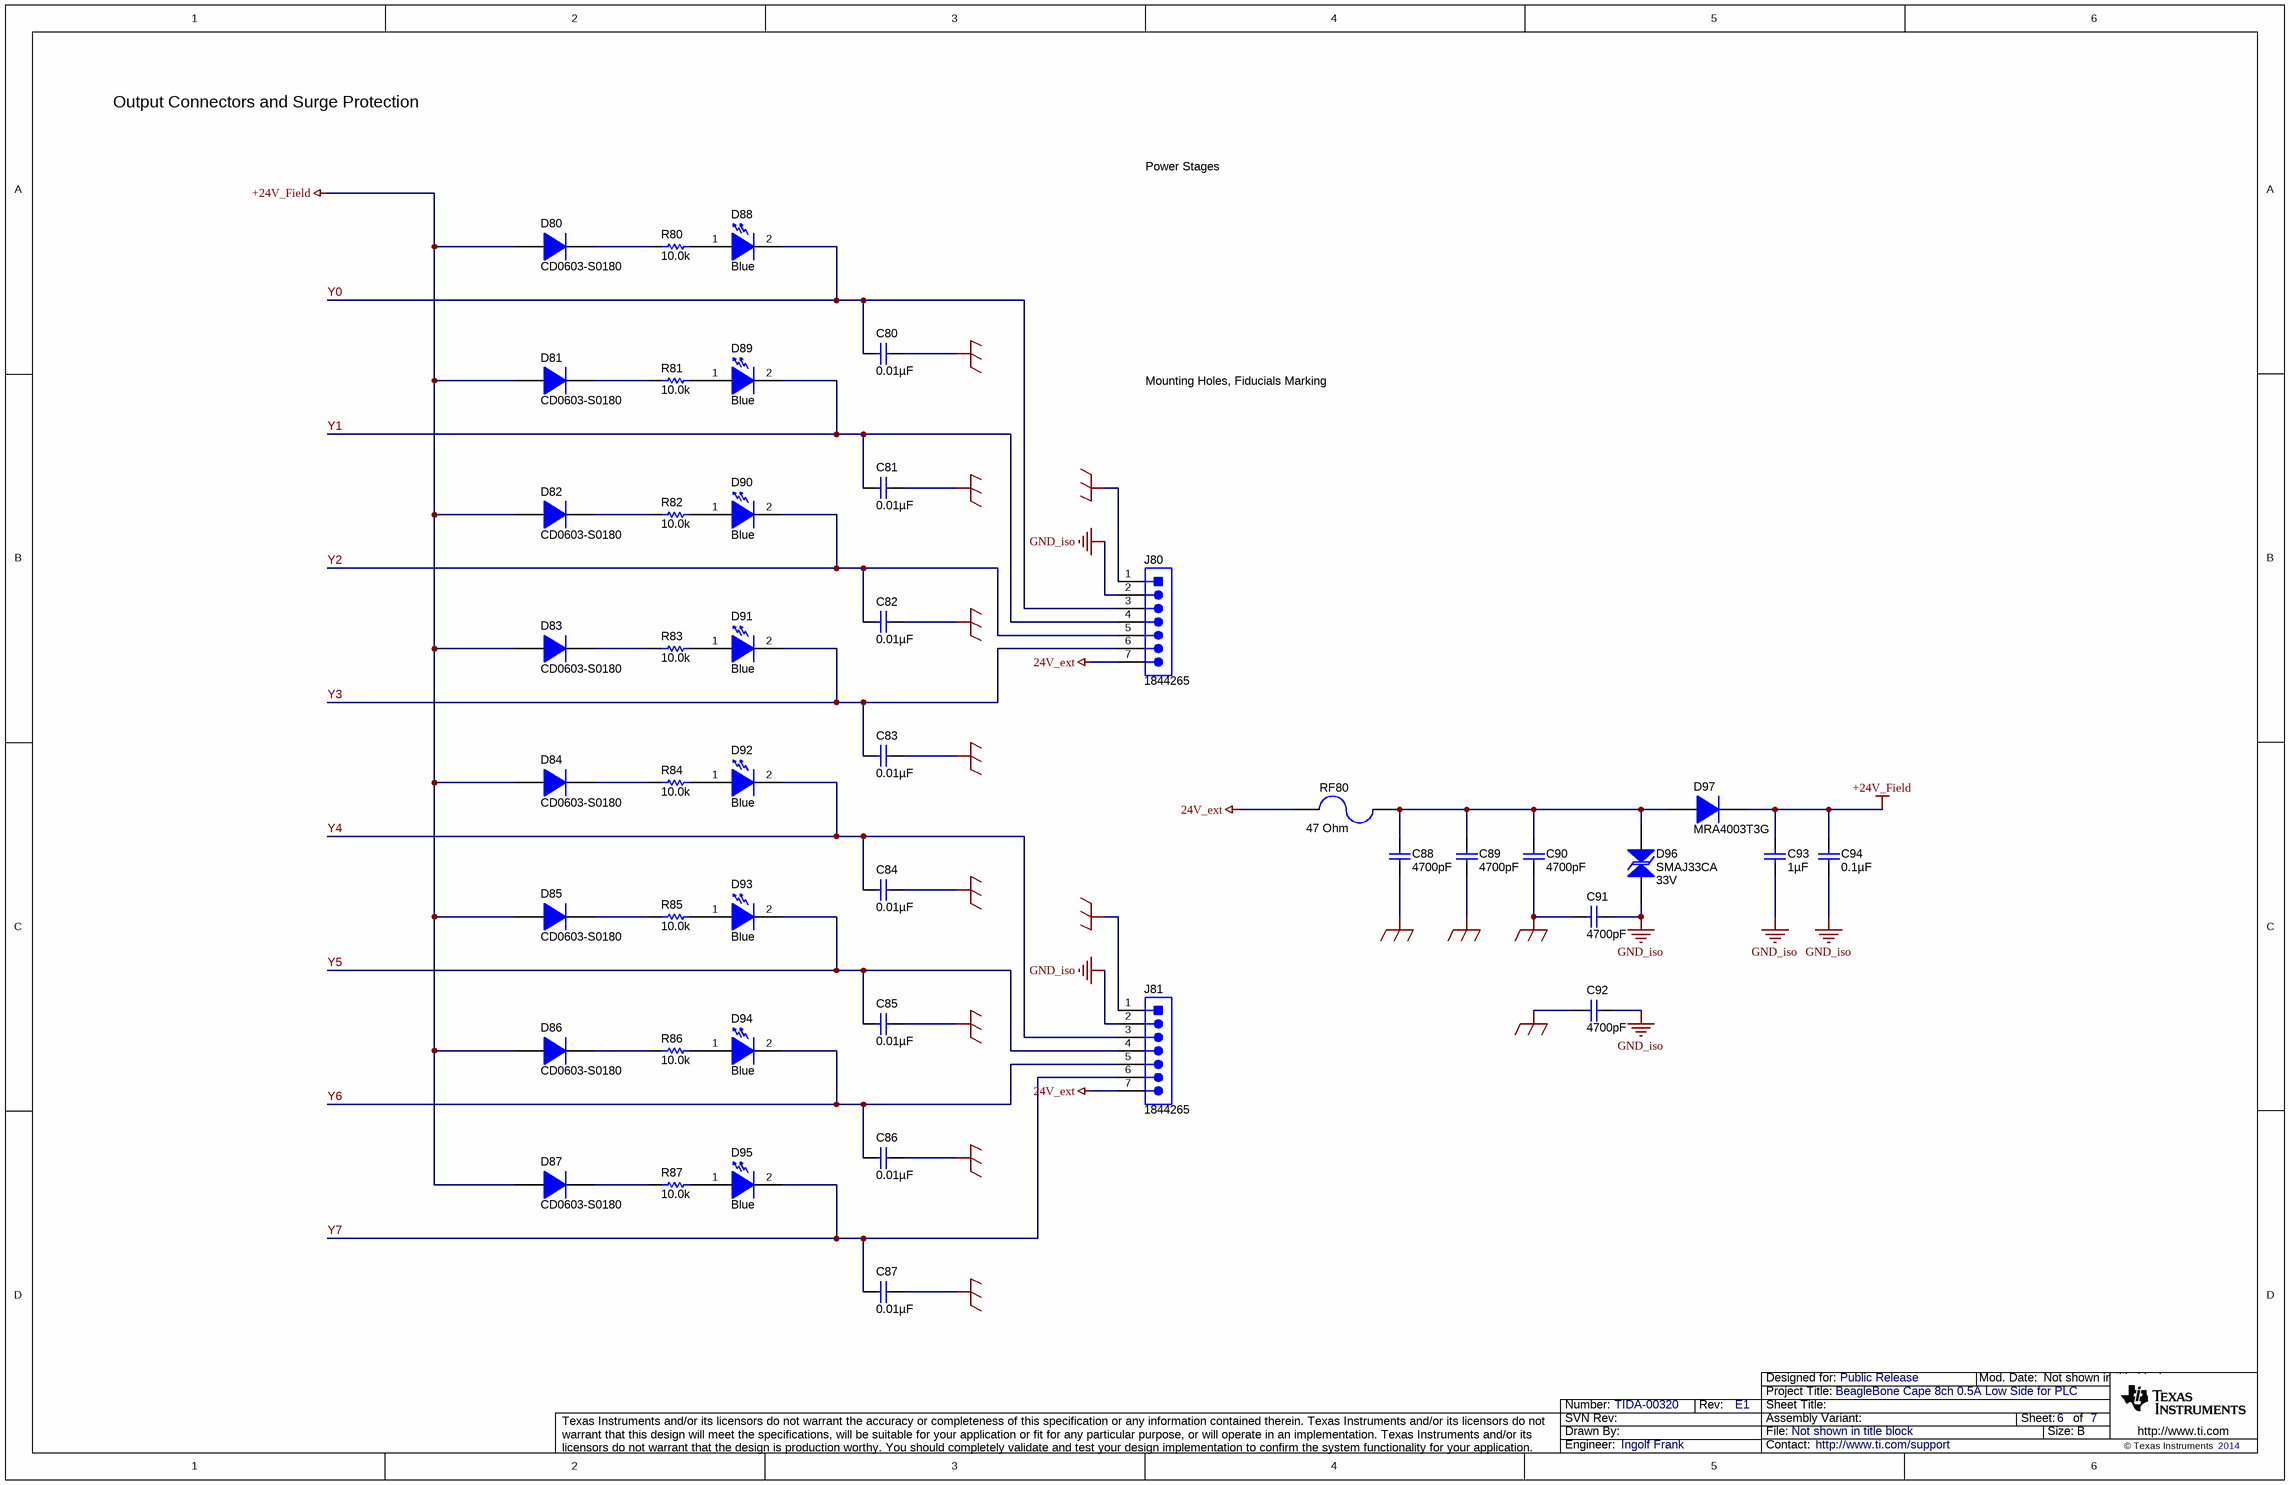
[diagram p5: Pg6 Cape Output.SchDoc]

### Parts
C80  ValueDisplayed: 0.01µF  [0603]  (hidden comment: C1608X7R2A103M)
C81  ValueDisplayed: 0.01µF  [0603]  (hidden comment: C1608X7R2A103M)
C82  ValueDisplayed: 0.01µF  [0603]  (hidden comment: C1608X7R2A103M)
C83  ValueDisplayed: 0.01µF  [0603]  (hidden comment: C1608X7R2A103M)
C84  ValueDisplayed: 0.01µF  [0603]  (hidden comment: C1608X7R2A103M)
C85  ValueDisplayed: 0.01µF  [0603]  (hidden comment: C1608X7R2A103M)
C86  ValueDisplayed: 0.01µF  [0603]  (hidden comment: C1608X7R2A103M)
C87  ValueDisplayed: 0.01µF  [0603]  (hidden comment: C1608X7R2A103M)
C88  ValueDisplayed: 4700pF  [0603]  (hidden comment: C1608X8R2A472K)
C89  ValueDisplayed: 4700pF  [0603]  (hidden comment: C1608X8R2A472K)
C90  ValueDisplayed: 4700pF  [0603]  (hidden comment: C1608X8R2A472K)
C91  ValueDisplayed: 4700pF  [0603]  (hidden comment: C1608X8R2A472K)
C92  ValueDisplayed: 4700pF  [0603]  (hidden comment: C1608X8R2A472K)
C93  ValueDisplayed: 1µF  [0805_HV]  (hidden comment: CL21B105KBFNNNE)
C94  ValueDisplayed: 0.1µF  [0603]  (hidden comment: C0603C104K5RACTU)
D80  CD0603-S0180  [Diode_0603]
D81  CD0603-S0180  [Diode_0603]
D82  CD0603-S0180  [Diode_0603]
D83  CD0603-S0180  [Diode_0603]
D84  CD0603-S0180  [Diode_0603]
D85  CD0603-S0180  [Diode_0603]
D86  CD0603-S0180  [Diode_0603]
D87  CD0603-S0180  [Diode_0603]
D88  value Blue  [LB Q39G_BLUE]  (hidden comment: LB Q39G-L2N2-35-1)
D89  value Blue  [LB Q39G_BLUE]  (hidden comment: LB Q39G-L2N2-35-1)
D90  value Blue  [LB Q39G_BLUE]  (hidden comment: LB Q39G-L2N2-35-1)
D91  value Blue  [LB Q39G_BLUE]  (hidden comment: LB Q39G-L2N2-35-1)
D92  value Blue  [LB Q39G_BLUE]  (hidden comment: LB Q39G-L2N2-35-1)
D93  value Blue  [LB Q39G_BLUE]  (hidden comment: LB Q39G-L2N2-35-1)
D94  value Blue  [LB Q39G_BLUE]  (hidden comment: LB Q39G-L2N2-35-1)
D95  value Blue  [LB Q39G_BLUE]  (hidden comment: LB Q39G-L2N2-35-1)
D96  SMAJ33CA  value 33V  [SMA]
D97  MRA4003T3G  [SMA]
J80  1844265  [Phoenix_1844265]
J81  1844265  [Phoenix_1844265]
R80  value 10.0k  [0603]  (hidden comment: CRCW060310K0FKEA)
R81  value 10.0k  [0603]  (hidden comment: CRCW060310K0FKEA)
R82  value 10.0k  [0603]  (hidden comment: CRCW060310K0FKEA)
R83  value 10.0k  [0603]  (hidden comment: CRCW060310K0FKEA)
R84  value 10.0k  [0603]  (hidden comment: CRCW060310K0FKEA)
R85  value 10.0k  [0603]  (hidden comment: CRCW060310K0FKEA)
R86  value 10.0k  [0603]  (hidden comment: CRCW060310K0FKEA)
R87  value 10.0k  [0603]  (hidden comment: CRCW060310K0FKEA)
RF80  47 Ohm  [EMC2]

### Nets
24V_ext: J80.7 J81.7 RF80.2
+24V_Field: C93.1 C94.1 D80.2(A) D81.2(A) D82.2(A) D83.2(A) D84.2(A) D85.2(A) D86.2(A) D87.2(A) D97.1(K)
GND_EARTH: C80.2 C81.2 C82.2 C83.2 C84.2 C85.2 C86.2 C87.2 C88.2 C89.2 C90.2 C91.2 C92.2 J80.1 J81.1
GND_iso: C91.1 C92.1 C93.2 C94.2 D96.1 J80.2 J81.2
Y0: C80.1 D88.2(K) J80.3
Y1: C81.1 D89.2(K) J80.4
Y2: C82.1 D90.2(K) J80.5
Y3: C83.1 D91.2(K) J80.6
Y4: C84.1 D92.2(K) J81.3
Y5: C85.1 D93.2(K) J81.4
Y6: C86.1 D94.2(K) J81.5
Y7: C87.1 D95.2(K) J81.6
NetC88_1: C88.1 C89.1 C90.1 D96.2 D97.2(A) RF80.1
NetD80_1: D80.1(K) R80.2
NetD81_1: D81.1(K) R81.2
NetD82_1: D82.1(K) R82.2
NetD83_1: D83.1(K) R83.2
NetD84_1: D84.1(K) R84.2
NetD85_1: D85.1(K) R85.2
NetD86_1: D86.1(K) R86.2
NetD87_1: D87.1(K) R87.2
NetD88_1: D88.1(A) R80.1
NetD89_1: D89.1(A) R81.1
NetD90_1: D90.1(A) R82.1
NetD91_1: D91.1(A) R83.1
NetD92_1: D92.1(A) R84.1
NetD93_1: D93.1(A) R85.1
NetD94_1: D94.1(A) R86.1
NetD95_1: D95.1(A) R87.1

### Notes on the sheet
- Output Connectors and Surge Protection
- Power Stages
- Mounting Holes, Fiducials Marking

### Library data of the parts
C80-C87 = C1608X7R2A103M: CAP, CERM, 0.01 µF, 100 V, +/- 20%, X7R, 0603; Manufacturer: TDK; Polarized: N; CompType: Capacitor; Value: 0.01uF; U/M: EA; Cap_F: 0.00000001; Tolerance_%: 20; ESR_ohm: 0.0661; Value1: 0.0661 ohm; VDC_V: 100; Value2: 100V; TaMin_C: -55; TaMax_C: 125
C88-C92 = C1608X8R2A472K: CAP, CERM, 4700 pF, 100 V, +/- 10%, X8R, 0603; Manufacturer: TDK; Polarized: N; CompType: Capacitor; Value: 4700pF; U/M: EA; Cap_F: 0.0000000047; Tolerance_%: 10; ESR_ohm: 0.0973; Value1: 0.0973 ohm; VDC_V: 100; Value2: 100V; TaMin_C: -55; TaMax_C: 150
C93 = CL21B105KBFNNNE: CAP, CERM, 1 µF, 50 V, +/- 10%, X7R, 0805; Manufacturer: Samsung; Polarized: N; CompType: Capacitor; Value: 1uF; U/M: EA; Cap_F: 0.000001; Tolerance_%: 10; Value1: Unknown; VDC_V: 50; Value2: 50V; TaMin_C: -55; TaMax_C: 125; Cap_Case: 0805
C94 = C0603C104K5RACTU: as C48 on sheet Pg4 Cape Power Supply
D80-D87 = CD0603-S0180: Diode, Switching, 90V, 0.1A, 0603 Diode; Manufacturer: Bourns; U/M: EA; Vf_V: 1; Value2: 1V; Io_A: 0.1; Vr_V: 90; TJmax_C: 125
D88-D95 = LB Q39G-L2N2-35-1: LED, Blue, SMD; Manufacturer: OSRAM; Vf_V: 2.85; Value2: 2.85V; Io_A: 0.15; Tjmax_C: 95; Value1: W; U/M: EA
D96 = SMAJ33CA: Diode, TVS, Bi, 33V, 400W, SMA; Manufacturer: Littelfuse; U/M: EA; Power_W: 400; Vr_V: 33; RJA_CperW: 120
D97 = MRA4003T3G: Diode, Standard Recovery Rectifier, 300V, 1A, SMA; Manufacturer: ON Semiconductor; U/M: EA; Vf_V: 1.1; Value2: 1.1V; Io_A: 1; Vr_V: 300; TJmax_C: 175; RJC_CperW: 16.2
J80 J81 = 1844265: Header (Shrouded), 3.5 mm, 7x1, R/A, TH; Manufacturer: Phoenix Contact; Alternate PartNumber: MC 1,5/ 7-G-3,5; SymbolCreator: a0411947; U/M: EA
R80-R87 = CRCW060310K0FKEA: RES, 10.0k ohm, 1%, 0.1W, 0603; Manufacturer: Vishay-Dale; CompType: Resistor; Res_ohm: 10000; Value_Code: 10k0; Tolerance_%: 1; Power_W: 0.1; VDC_V: 75; TempCo: 100 ppm/C; EIA_Code: E96; U/M: EA
RF80 = EMC2-47RKI: RES, 47 ohm, 10%, 2W, Fusible, TH; Manufacturer: TT Electronics/IRC; SymbolCreator: a0412235; CompType: Fusible Resistor; Res_ohm: 47; Value: 47; Value_Code: 47R0; Tolerance_%: 10; Power_W: 2; TempCo: 100 ppm/C; U/M: EA

## Sheet Pg7 Hardware.SchDoc
size 431 x 279 mm; Date: Not shown in title block; ApprovedBy: Not shown in title block; CheckedBy: Not shown in title block; Author: Not shown in title block; CompanyName: Not shown in title block; Engineer: Not shown in title block; Organization: Not shown in title block; Address1: Not shown in title block; Address2: Not shown in title block; Address3: Not shown in title block; Address4: Not shown in title block; DocumentNumber: 7; Revision: Use project parameter SCH_Rev; SheetNumber: 7; SheetTotal: 7; PageSetup: Record=PageOptions¦CenterHorizontal=True¦CenterVertical=True¦PrintScale=1.00¦XCorrection=1.00¦YCorrection=1.00¦PrintKind=0¦BorderSize=5000000¦LeftOffset=0¦BottomOffset=0¦Orientation=2¦PaperLength=1000¦PaperWidth=1000¦Scale=100¦PaperSource=15¦PrintQuality=600¦MediaType=1¦DitherType=10¦PaperKind=Letter¦PrintScaleMode=1
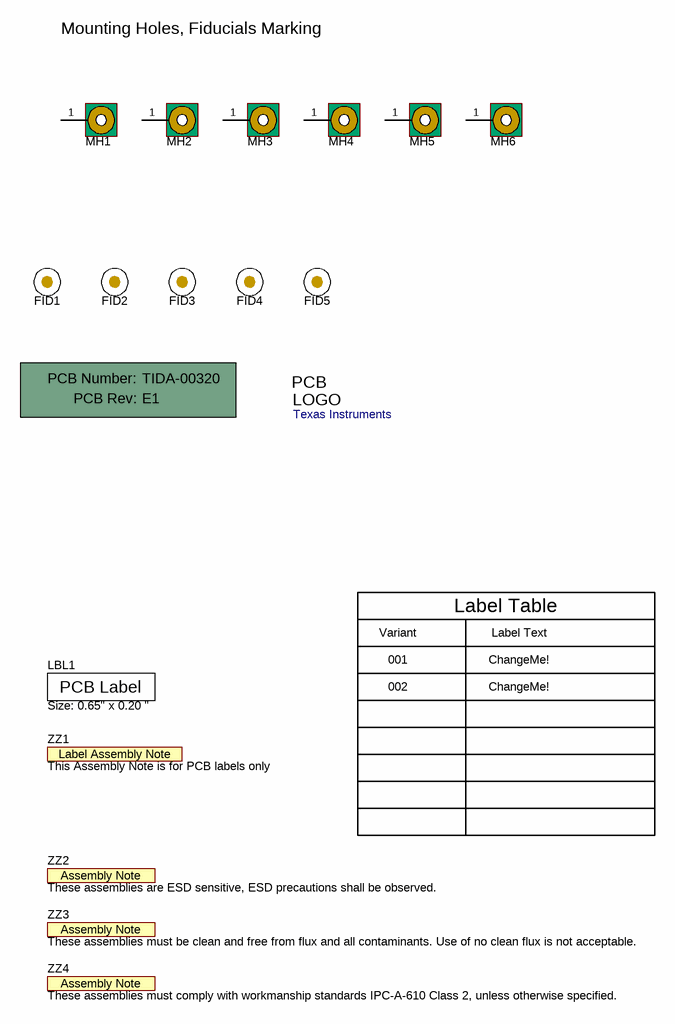
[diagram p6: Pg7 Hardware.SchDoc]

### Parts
!PCB1  Printed Circuit Board  (value not drawn)  (mechanical)
FID1  Fiducial  [Fiducial10-20]  (value not drawn)
FID2  Fiducial  [Fiducial10-20]  (value not drawn)
FID3  Fiducial  [Fiducial10-20]  (value not drawn)
FID4  Fiducial  [Fiducial10-20]  (value not drawn)
FID5  Fiducial  [Fiducial10-20]  (value not drawn)
LBL1  Size: 0.65" x 0.20 "  [Label_650x200]
Logo1  Texas Instruments  [TI_Stacked_SolderMask_Small]  (no BOM)
MH1  MTG_Pads  [MTGP_4-40_PanHead]  (value not drawn)  (no BOM)
MH2  MTG_Pads  [MTGP_4-40_PanHead]  (value not drawn)  (no BOM)
MH3  MTG_Pads  [MTGP_4-40_PanHead]  (value not drawn)  (no BOM)
MH4  MTG_Pads  [MTGP_4-40_PanHead]  (value not drawn)  (no BOM)
MH5  MTG_Pads  [MTGP_4-40_PanHead]  (value not drawn)  (no BOM)
MH6  MTG_Pads  [MTGP_4-40_PanHead]  (value not drawn)  (no BOM)
ZZ1  This Assembly Note is for PCB labels only  [AssemblyNoteLabel]  (no BOM)
ZZ2  These assemblies are ESD sensitive, ESD precautions shall be observed.  [AssemblyNote]  (no BOM)
ZZ3  These assemblies must be clean and free from flux and all contaminants. Use of no clean flux is not acceptable.  [AssemblyNote]  (no BOM)
ZZ4  These assemblies must comply with workmanship standards IPC-A-610 Class 2, unless otherwise specified.  [AssemblyNote]  (no BOM)

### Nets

Not connected (* = marked no-connect by the designer): MH1 1; MH2 1; MH3 1; MH4 1; MH5 1; MH6 1

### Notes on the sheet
- Mounting Holes, Fiducials Marking
- Variant
- Label Table
- Label Text
- 001
- 002
- ChangeMe!

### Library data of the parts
!PCB1 = PCB: Manufacturer: Any; PartNumber: TIDA-00320; SymbolCreator: a0412235
FID1-FID5 = Fiducial: Fiducial mark.  There is nothing to buy or mount.; SymbolCreator: codlsc
LBL1 = THT-14-423-10: Thermal Transfer Printable Labels, 0.650" W x 0.200" H - 10,000 per roll; Manufacturer: Brady; SymbolCreator: a0412235; CompType: Label
Logo1 = TI_Logo: Texas Instrument Corporate Signature; SymbolCreator: a0412235
MH1-MH6 = Mounting Hole (Imperial) with Pads: PCB Mounting Hole; Manufacturer: Any; SymbolCreator: a0412235
ZZ1 = AssemblyNoteLabel: SymbolCreator: a0412235
ZZ2-ZZ4 = AssemblyNote: SymbolCreator: codlsc

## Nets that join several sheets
+5V_iso: Pg4 Cape Power Supply (13 pins), Pg5 Cape Power Stages (R60.1 R61.1)
+24V_Field: Pg4 Cape Power Supply (L40.1), Pg5 Cape Power Stages (L60.1 L61.1), Pg6 Cape Output (11 pins)
DGND: Pg3 BB Connectors (14 pins), Pg4 Cape Power Supply (10 pins)
GND_iso: Pg4 Cape Power Supply (21 pins), Pg5 Cape Power Stages (12 pins), Pg6 Cape Output (7 pins)
VDD_3V3B: Pg3 BB Connectors (10 pins), Pg4 Cape Power Supply (6 pins)
/FAULT0: Pg4 Cape Power Supply (U42.11), Pg5 Cape Power Stages (R61.2 U61.16)
/FAULT1: Pg4 Cape Power Supply (U42.12), Pg5 Cape Power Stages (R60.2 U60.16)
GPIO0_26: Pg3 BB Connectors (J20.14), Pg4 Cape Power Supply (U40.4)
GPIO0_27: Pg3 BB Connectors (J20.17), Pg4 Cape Power Supply (U40.3)
GPIO1_16: Pg3 BB Connectors (J21.15), Pg4 Cape Power Supply (U41.3)
GPIO1_17: Pg3 BB Connectors (J21.23), Pg4 Cape Power Supply (U41.6)
GPIO1_28: Pg3 BB Connectors (J21.12), Pg4 Cape Power Supply (U42.3)
GPIO1_29: Pg3 BB Connectors (J20.26), Pg4 Cape Power Supply (U42.6)
GPIO2_1: Pg3 BB Connectors (J20.18), Pg4 Cape Power Supply (U42.5)
In_Y0: Pg4 Cape Power Supply (U42.13), Pg5 Cape Power Stages (U61.14)
In_Y1: Pg4 Cape Power Supply (U42.14), Pg5 Cape Power Stages (U61.13)
In_Y2: Pg4 Cape Power Supply (U41.11), Pg5 Cape Power Stages (U61.11)
In_Y3: Pg4 Cape Power Supply (U41.12), Pg5 Cape Power Stages (U61.10)
In_Y4: Pg4 Cape Power Supply (U40.11), Pg5 Cape Power Stages (U60.14)
In_Y5: Pg4 Cape Power Supply (U40.12), Pg5 Cape Power Stages (U60.13)
In_Y6: Pg4 Cape Power Supply (U40.13), Pg5 Cape Power Stages (U60.11)
In_Y7: Pg4 Cape Power Supply (U40.14), Pg5 Cape Power Stages (U60.10)
nENBL: Pg4 Cape Power Supply (U41.14), Pg5 Cape Power Stages (U60.8 U61.8)
RESET: Pg4 Cape Power Supply (U41.13), Pg5 Cape Power Stages (U60.9 U61.9)
SYS_RESETn: Pg3 BB Connectors (J21.10), Pg4 Cape Power Supply (U42.7)
TIMER5: Pg3 BB Connectors (J20.9), Pg4 Cape Power Supply (U40.6)
TIMER6: Pg3 BB Connectors (J20.10), Pg4 Cape Power Supply (U40.5)
TIMER7: Pg3 BB Connectors (J20.8), Pg4 Cape Power Supply (U42.4)
UART2_RXD: Pg3 BB Connectors (J21.22), Pg4 Cape Power Supply (U41.5)
UART2_TXD: Pg3 BB Connectors (J21.21), Pg4 Cape Power Supply (U41.4)
Y0: Pg5 Cape Power Stages (U61.3), Pg6 Cape Output (C80.1 D88.2 J80.3)
Y1: Pg5 Cape Power Stages (U61.4), Pg6 Cape Output (C81.1 D89.2 J80.4)
Y2: Pg5 Cape Power Stages (U61.6), Pg6 Cape Output (C82.1 D90.2 J80.5)
Y3: Pg5 Cape Power Stages (U61.7), Pg6 Cape Output (C83.1 D91.2 J80.6)
Y4: Pg5 Cape Power Stages (U60.3), Pg6 Cape Output (C84.1 D92.2 J81.3)
Y5: Pg5 Cape Power Stages (U60.4), Pg6 Cape Output (C85.1 D93.2 J81.4)
Y6: Pg5 Cape Power Stages (U60.6), Pg6 Cape Output (C86.1 D94.2 J81.5)
Y7: Pg5 Cape Power Stages (U60.7), Pg6 Cape Output (C87.1 D95.2 J81.6)

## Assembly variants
001: not fitted FID1 FID2 FID3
